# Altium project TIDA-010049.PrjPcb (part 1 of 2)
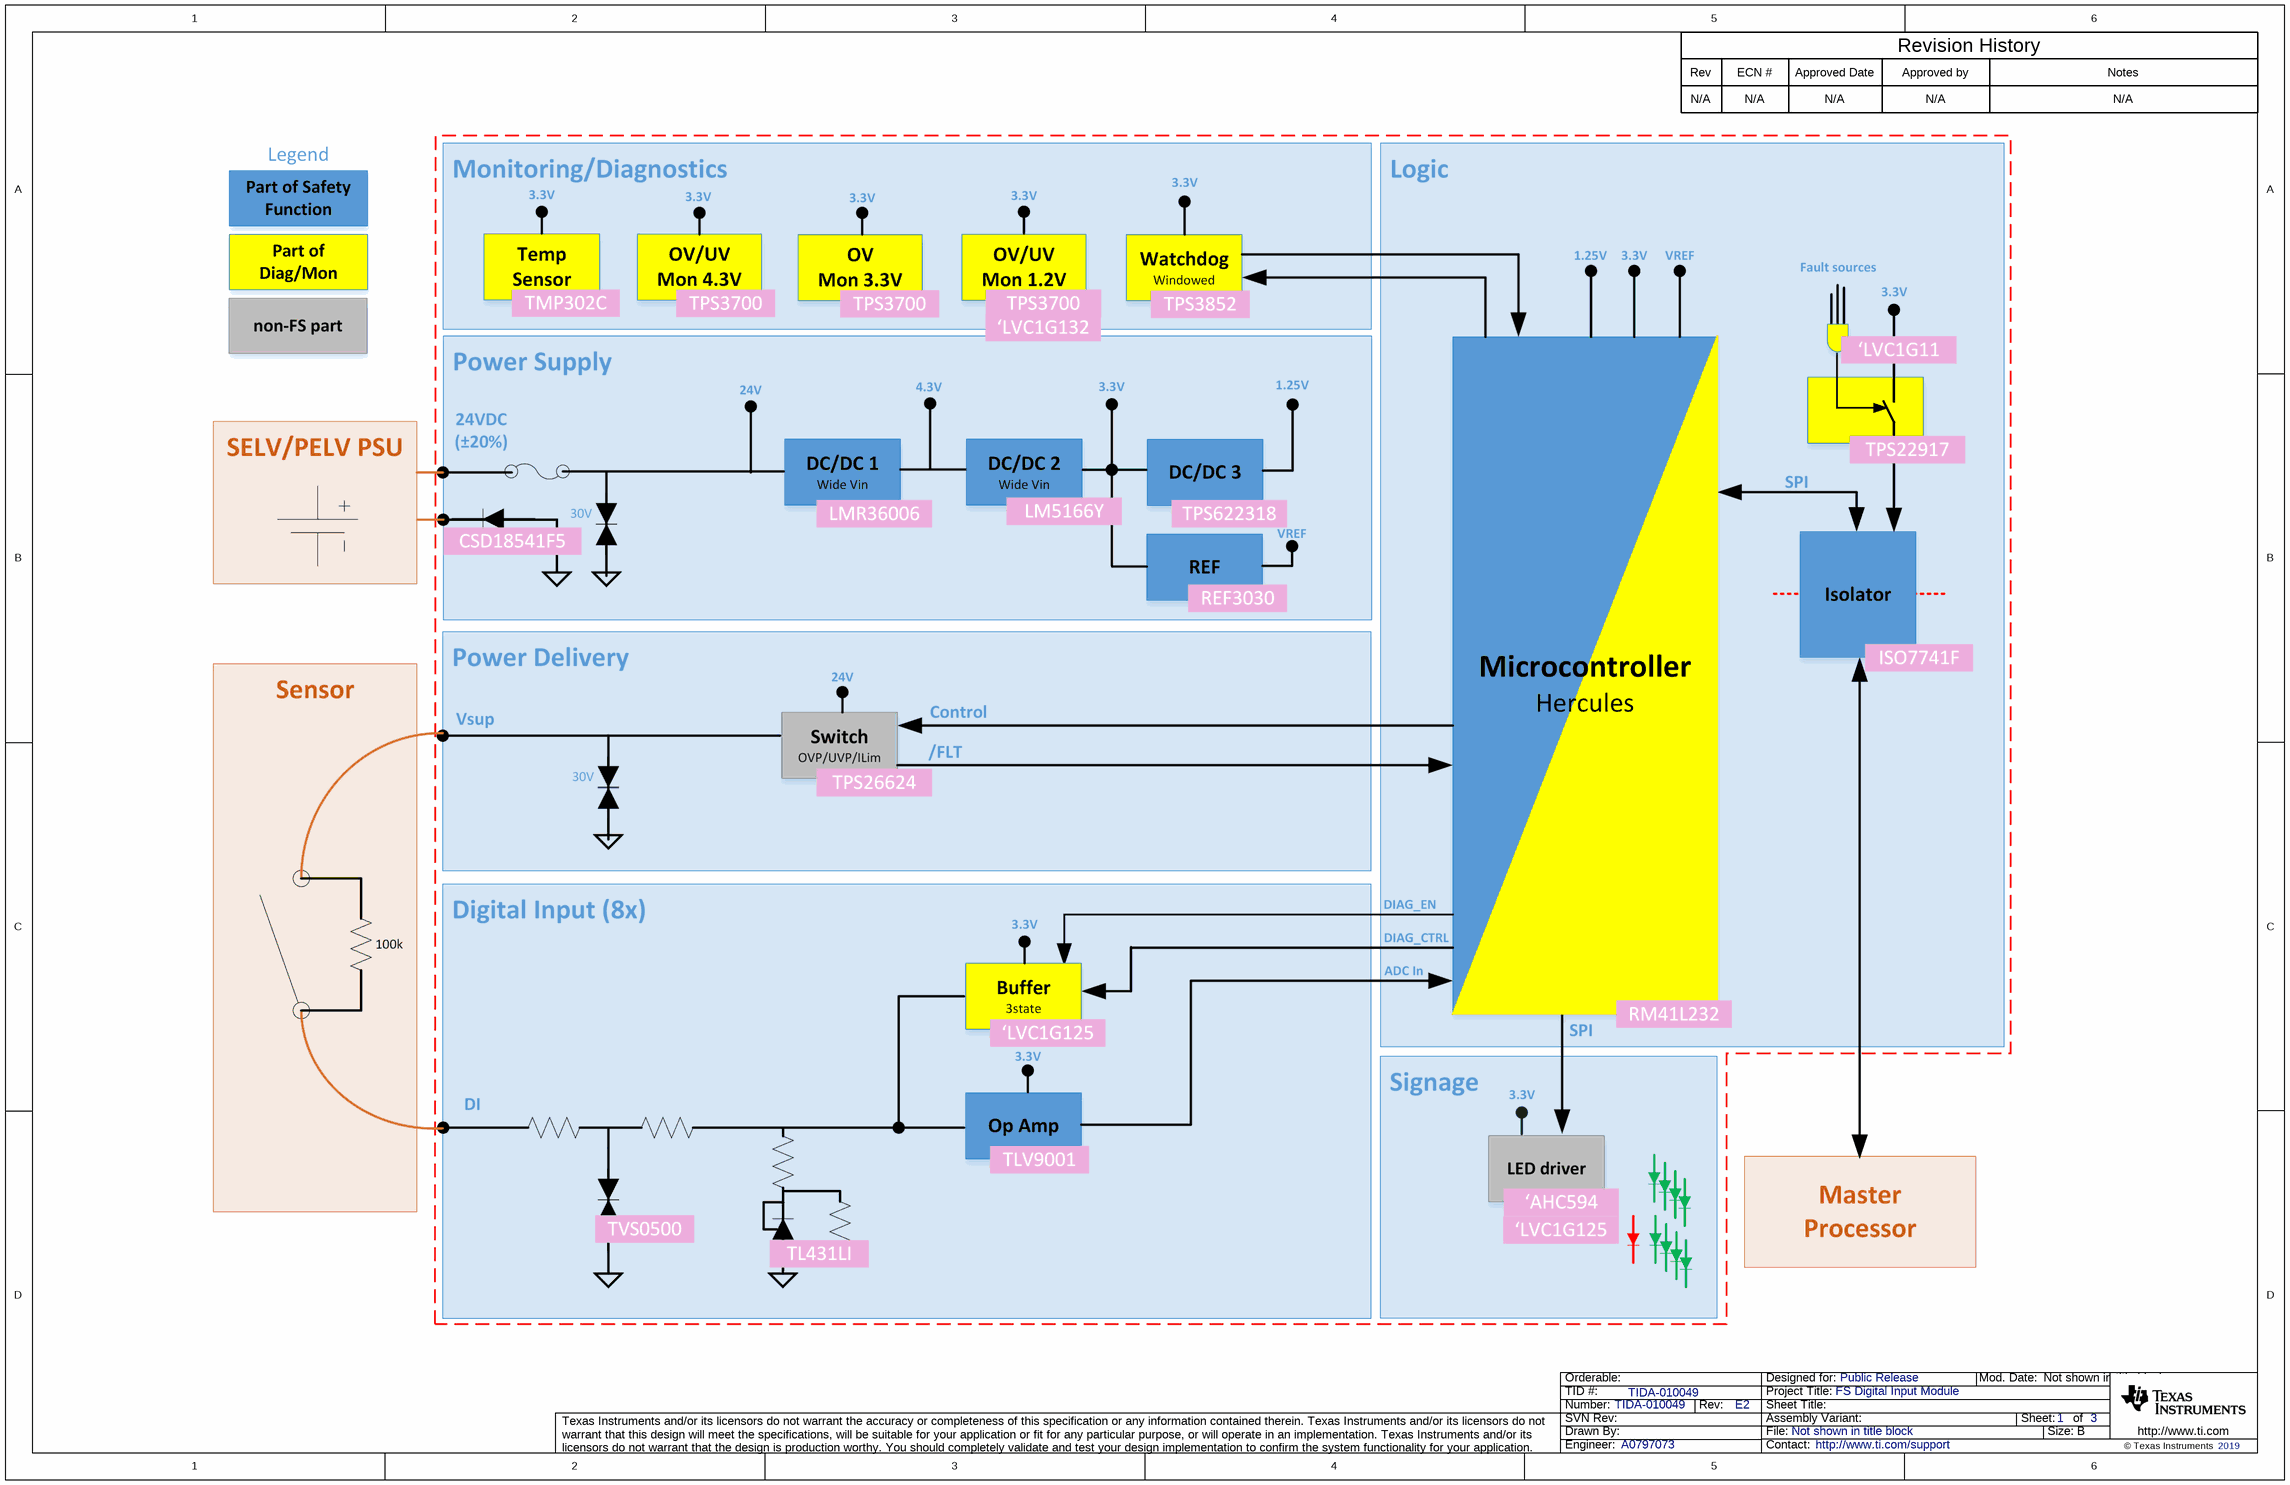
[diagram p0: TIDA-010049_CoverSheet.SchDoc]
CopyrightYear: 2019; PCB_Layout: A0797073; PCB_Rev: E2; PRJ_Customer: Public Release; PRJ_Engineer: A0797073; PRJ_Number: TIDA-010049; PRJ_Title: FS Digital Input Module; SCH_Rev: E2; TechSupport: http://www.ti.com/support; TID: TIDA-010049
7 sheets, 310 parts. Net scope: hierarchical (ports join the sheet entries above them; power ports are global).
Board file: TIDA-010049.PcbDoc
Sheets:
  TIDA-010049_CoverSheet.SchDoc
  TIDA-010049_Top.SchDoc
    U_TIDACBL-0053_Hercules = TIDA-010049_Hercules.SchDoc
    U_TIDACBL-0053_Power = TIDA-010049_Power.SchDoc
    DI1 = TIDA-010049_DigitalInputChan.SchDoc
    DI2 = TIDA-010049_DigitalInputChan.SchDoc
    DI3 = TIDA-010049_DigitalInputChan.SchDoc
    DI4 = TIDA-010049_DigitalInputChan.SchDoc
    DI5 = TIDA-010049_DigitalInputChan.SchDoc
    DI6 = TIDA-010049_DigitalInputChan.SchDoc
    DI7 = TIDA-010049_DigitalInputChan.SchDoc
    DI8 = TIDA-010049_DigitalInputChan.SchDoc
    U_TIDACBL-0053_LED = TIDA-010049_LED.SchDoc
    U_TIDA-010049_Hardware = TIDA-010049_Hardware.SchDoc

## Sheet TIDA-010049_CoverSheet.SchDoc
size 431 x 279 mm; Date: Not shown in title block; ApprovedBy: Not shown in title block; CheckedBy: Not shown in title block; Author: Not shown in title block; CompanyName: Not shown in title block; Engineer: Not shown in title block; Organization: Not shown in title block; Address1: Not shown in title block; Address2: Not shown in title block; Address3: Not shown in title block; Address4: Not shown in title block; DocumentNumber: 1; Revision: Use project parameter SCH_Rev; SheetNumber: 1; SheetTotal: 3; PageSetup: Record=PageOptions¦CenterHorizontal=True¦CenterVertical=True¦PrintScale=1.00¦XCorrection=1.00¦YCorrection=1.00¦PrintKind=0¦BorderSize=5000000¦LeftOffset=0¦BottomOffset=0¦Orientation=2¦PaperLength=1000¦PaperWidth=1000¦Scale=100¦PaperSource=15¦PrintQuality=600¦MediaType=1¦DitherType=10¦PaperKind=Letter¦PrintScaleMode=1

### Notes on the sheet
- Rev
- N/A
- ECN #
- Approved Date
- Approved by
- Revision History
- Notes

## Sheet TIDA-010049_Top.SchDoc
size 431 x 279 mm; Date: Not shown in title block; ApprovedBy: Not shown in title block; CheckedBy: Not shown in title block; Author: Not shown in title block; CompanyName: Not shown in title block; Engineer: Not shown in title block; Organization: Not shown in title block; Address1: Not shown in title block; Address2: Not shown in title block; Address3: Not shown in title block; Address4: Not shown in title block; DocumentNumber: 2; Revision: Use project parameter SCH_Rev; SheetNumber: 2; SheetTotal: 3; PageSetup: Record=PageOptions¦CenterHorizontal=True¦CenterVertical=True¦PrintScale=1.00¦XCorrection=1.00¦YCorrection=1.00¦PrintKind=0¦BorderSize=5000000¦LeftOffset=0¦BottomOffset=0¦Orientation=2¦PaperLength=1000¦PaperWidth=1000¦Scale=100¦PaperSource=15¦PrintQuality=600¦MediaType=1¦DitherType=10¦PaperKind=Letter¦PrintScaleMode=1
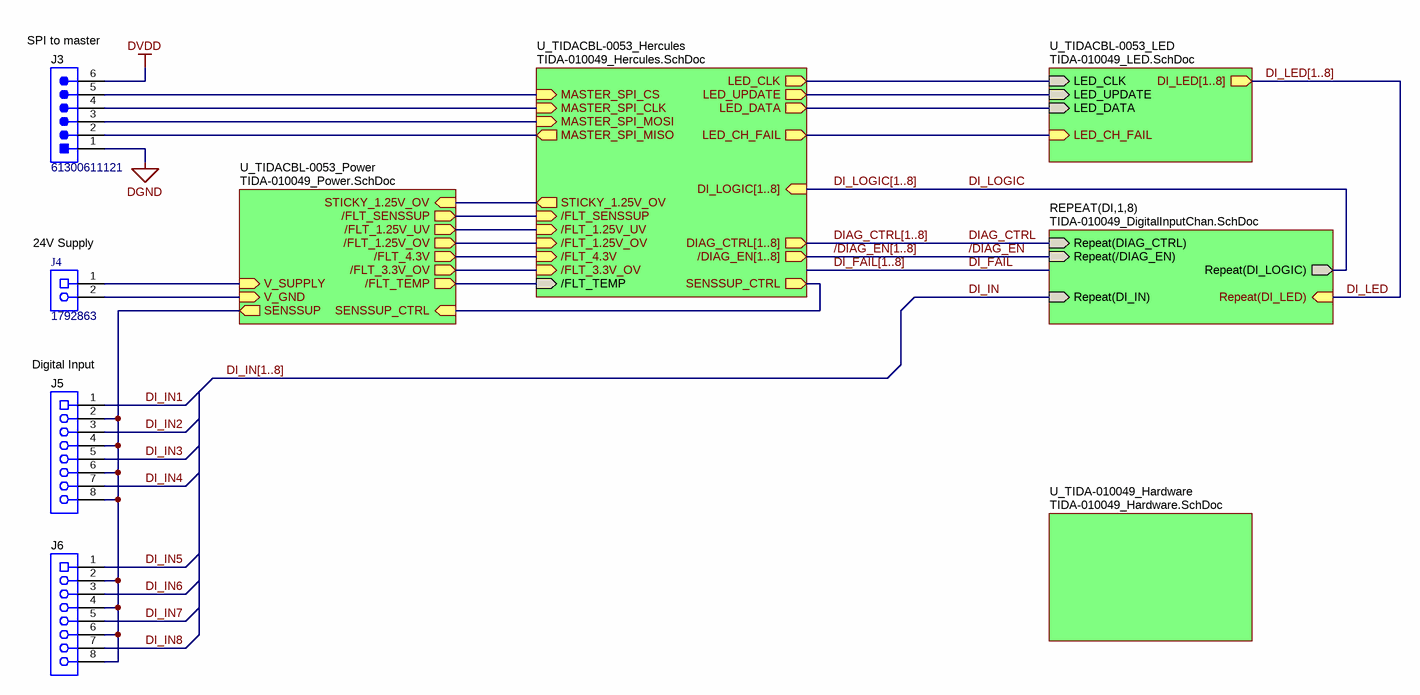
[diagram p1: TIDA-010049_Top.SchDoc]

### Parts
J3  61300611121  [WURTH_61300611121]
J4  1792863  [Phoenix_1792863]
J5  1990067  [Phoenix_1990067]  (value not drawn)
J6  1990067  [Phoenix_1990067]  (value not drawn)

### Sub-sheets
REPEAT(DI,1,8) = TIDA-010049_DigitalInputChan.SchDoc: Repeat(DI_IN) (in), Repeat(/DIAG_EN) (in), Repeat(DIAG_CTRL) (in), Repeat(DI_LOGIC) (out), Repeat(DI_LED) (in)
U_TIDA-010049_Hardware = TIDA-010049_Hardware.SchDoc: no entries
U_TIDACBL-0053_Hercules = TIDA-010049_Hercules.SchDoc: /FLT_TEMP (in), DIAG_CTRL[1..8] (out), /DIAG_EN[1..8] (out), MASTER_SPI_CLK (in), MASTER_SPI_MISO (out), MASTER_SPI_CS (in), MASTER_SPI_MOSI (in), /FLT_3.3V_OV (in), DI_LOGIC[1..8] (in), LED_CH_FAIL (out), LED_CLK (out), LED_DATA (out), LED_UPDATE (out), /FLT_4.3V (in), /FLT_SENSSUP (in), /FLT_1.25V_OV (in), SENSSUP_CTRL (out), STICKY_1.25V_OV (out), /FLT_1.25V_UV (in)
U_TIDACBL-0053_LED = TIDA-010049_LED.SchDoc: LED_UPDATE (in), LED_CLK (in), LED_DATA (in), LED_CH_FAIL (in), DI_LED[1..8] (out)
U_TIDACBL-0053_Power = TIDA-010049_Power.SchDoc: /FLT_TEMP (out), V_SUPPLY (in), /FLT_3.3V_OV (out), V_GND (in), /FLT_4.3V (out), SENSSUP (out), /FLT_SENSSUP (out), SENSSUP_CTRL (in), /FLT_1.25V_OV (out), /FLT_1.25V_UV (out), STICKY_1.25V_OV (in)

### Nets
DGND: J3.1
DVDD: J3.6
/FLT_1.25V_OV: sheet U_TIDACBL-0053_Hercules//FLT_1.25V_OV, sheet U_TIDACBL-0053_Power//FLT_1.25V_OV
/FLT_1.25V_UV: sheet U_TIDACBL-0053_Hercules//FLT_1.25V_UV, sheet U_TIDACBL-0053_Power//FLT_1.25V_UV
/FLT_3.3V_OV: sheet U_TIDACBL-0053_Hercules//FLT_3.3V_OV, sheet U_TIDACBL-0053_Power//FLT_3.3V_OV
/FLT_4.3V: sheet U_TIDACBL-0053_Hercules//FLT_4.3V, sheet U_TIDACBL-0053_Power//FLT_4.3V
/FLT_SENSSUP: sheet U_TIDACBL-0053_Hercules//FLT_SENSSUP, sheet U_TIDACBL-0053_Power//FLT_SENSSUP
/FLT_TEMP: sheet U_TIDACBL-0053_Hercules//FLT_TEMP, sheet U_TIDACBL-0053_Power//FLT_TEMP
DI_IN1: J5.1
DI_IN2: J5.3
DI_IN3: J5.5
DI_IN4: J5.7
DI_IN5: J6.1
DI_IN6: J6.3
DI_IN7: J6.5
DI_IN8: J6.7
LED_CH_FAIL: sheet U_TIDACBL-0053_Hercules/LED_CH_FAIL, sheet U_TIDACBL-0053_LED/LED_CH_FAIL
LED_CLK: sheet U_TIDACBL-0053_Hercules/LED_CLK, sheet U_TIDACBL-0053_LED/LED_CLK
LED_DATA: sheet U_TIDACBL-0053_Hercules/LED_DATA, sheet U_TIDACBL-0053_LED/LED_DATA
LED_UPDATE: sheet U_TIDACBL-0053_Hercules/LED_UPDATE, sheet U_TIDACBL-0053_LED/LED_UPDATE
MASTER_SPI_CLK: J3.4 ; sheet U_TIDACBL-0053_Hercules/MASTER_SPI_CLK
MASTER_SPI_CS: J3.5 ; sheet U_TIDACBL-0053_Hercules/MASTER_SPI_CS
MASTER_SPI_MISO: J3.2 ; sheet U_TIDACBL-0053_Hercules/MASTER_SPI_MISO
MASTER_SPI_MOSI: J3.3 ; sheet U_TIDACBL-0053_Hercules/MASTER_SPI_MOSI
SENSSUP: J5.2 J5.4 J5.6 J5.8 J6.2 J6.4 J6.6 J6.8 ; sheet U_TIDACBL-0053_Power/SENSSUP
SENSSUP_CTRL: sheet U_TIDACBL-0053_Hercules/SENSSUP_CTRL, sheet U_TIDACBL-0053_Power/SENSSUP_CTRL
STICKY_1.25V_OV: sheet U_TIDACBL-0053_Hercules/STICKY_1.25V_OV, sheet U_TIDACBL-0053_Power/STICKY_1.25V_OV
V_GND: J4.2 ; sheet U_TIDACBL-0053_Power/V_GND
V_SUPPLY: J4.1 ; sheet U_TIDACBL-0053_Power/V_SUPPLY

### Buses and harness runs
bus /DIAG_EN[1..8] = sheet U_TIDACBL-0053_Hercules//DIAG_EN[1..8]
bus DI_FAIL[1..8]
bus DI_IN[1..8]
bus DI_LED[1..8] = sheet U_TIDACBL-0053_LED/DI_LED[1..8]
bus DI_LOGIC[1..8] = sheet U_TIDACBL-0053_Hercules/DI_LOGIC[1..8]
bus DIAG_CTRL[1..8] = sheet U_TIDACBL-0053_Hercules/DIAG_CTRL[1..8]

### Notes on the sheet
- (near J3) SPI to master
- (near J4) 24V Supply
- (near J5) Digital Input

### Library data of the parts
J3 = CMP-0054801-2: Header, 2.54 mm, 6x1, Gold, TH; Manufacturer: Wurth Elektronik; Cert_UL: Y; Gender: Male; Row_Count: 1; Shrouded: N; Pitch_mm: 2.54
J4 = CMP-0055529-1: Terminal Block, 5mm, 2x1, R/A, TH; Manufacturer: Phoenix Contact; Cert_VDE: Y; CNHeader: FALSE; Current_A: 16A; Gender: Female; Voltage_V: 400V; Row_Count: 1; Pitch_mm: 5; CT: TRUE
J5 J6 = CMP-0055509-1: Terminal Block, 8x1, 2.5mm, Green, TH; Manufacturer: Phoenix Contact; CNHeader: FALSE; Current_A: 2A; Gender: Female; Cert_CSA: Y; Voltage_V: 300V; Row_Count: 1; Pitch_mm: 2.5; CT: TRUE

## Sheet TIDA-010049_Hercules.SchDoc
size 431 x 279 mm; Date: Not shown in title block; ApprovedBy: Not shown in title block; CheckedBy: Not shown in title block; Author: Not shown in title block; CompanyName: Not shown in title block; Engineer: Not shown in title block; Organization: Not shown in title block; Address1: Not shown in title block; Address2: Not shown in title block; Address3: Not shown in title block; Address4: Not shown in title block; DocumentNumber: 2; Revision: Use project parameter SCH_Rev; SheetNumber: 2; SheetTotal: 3; PageSetup: Record=PageOptions¦CenterHorizontal=True¦CenterVertical=True¦PrintScale=1.00¦XCorrection=1.00¦YCorrection=1.00¦PrintKind=0¦BorderSize=5000000¦LeftOffset=0¦BottomOffset=0¦Orientation=2¦PaperLength=1000¦PaperWidth=1000¦Scale=100¦PaperSource=15¦PrintQuality=600¦MediaType=1¦DitherType=10¦PaperKind=Letter¦PrintScaleMode=1
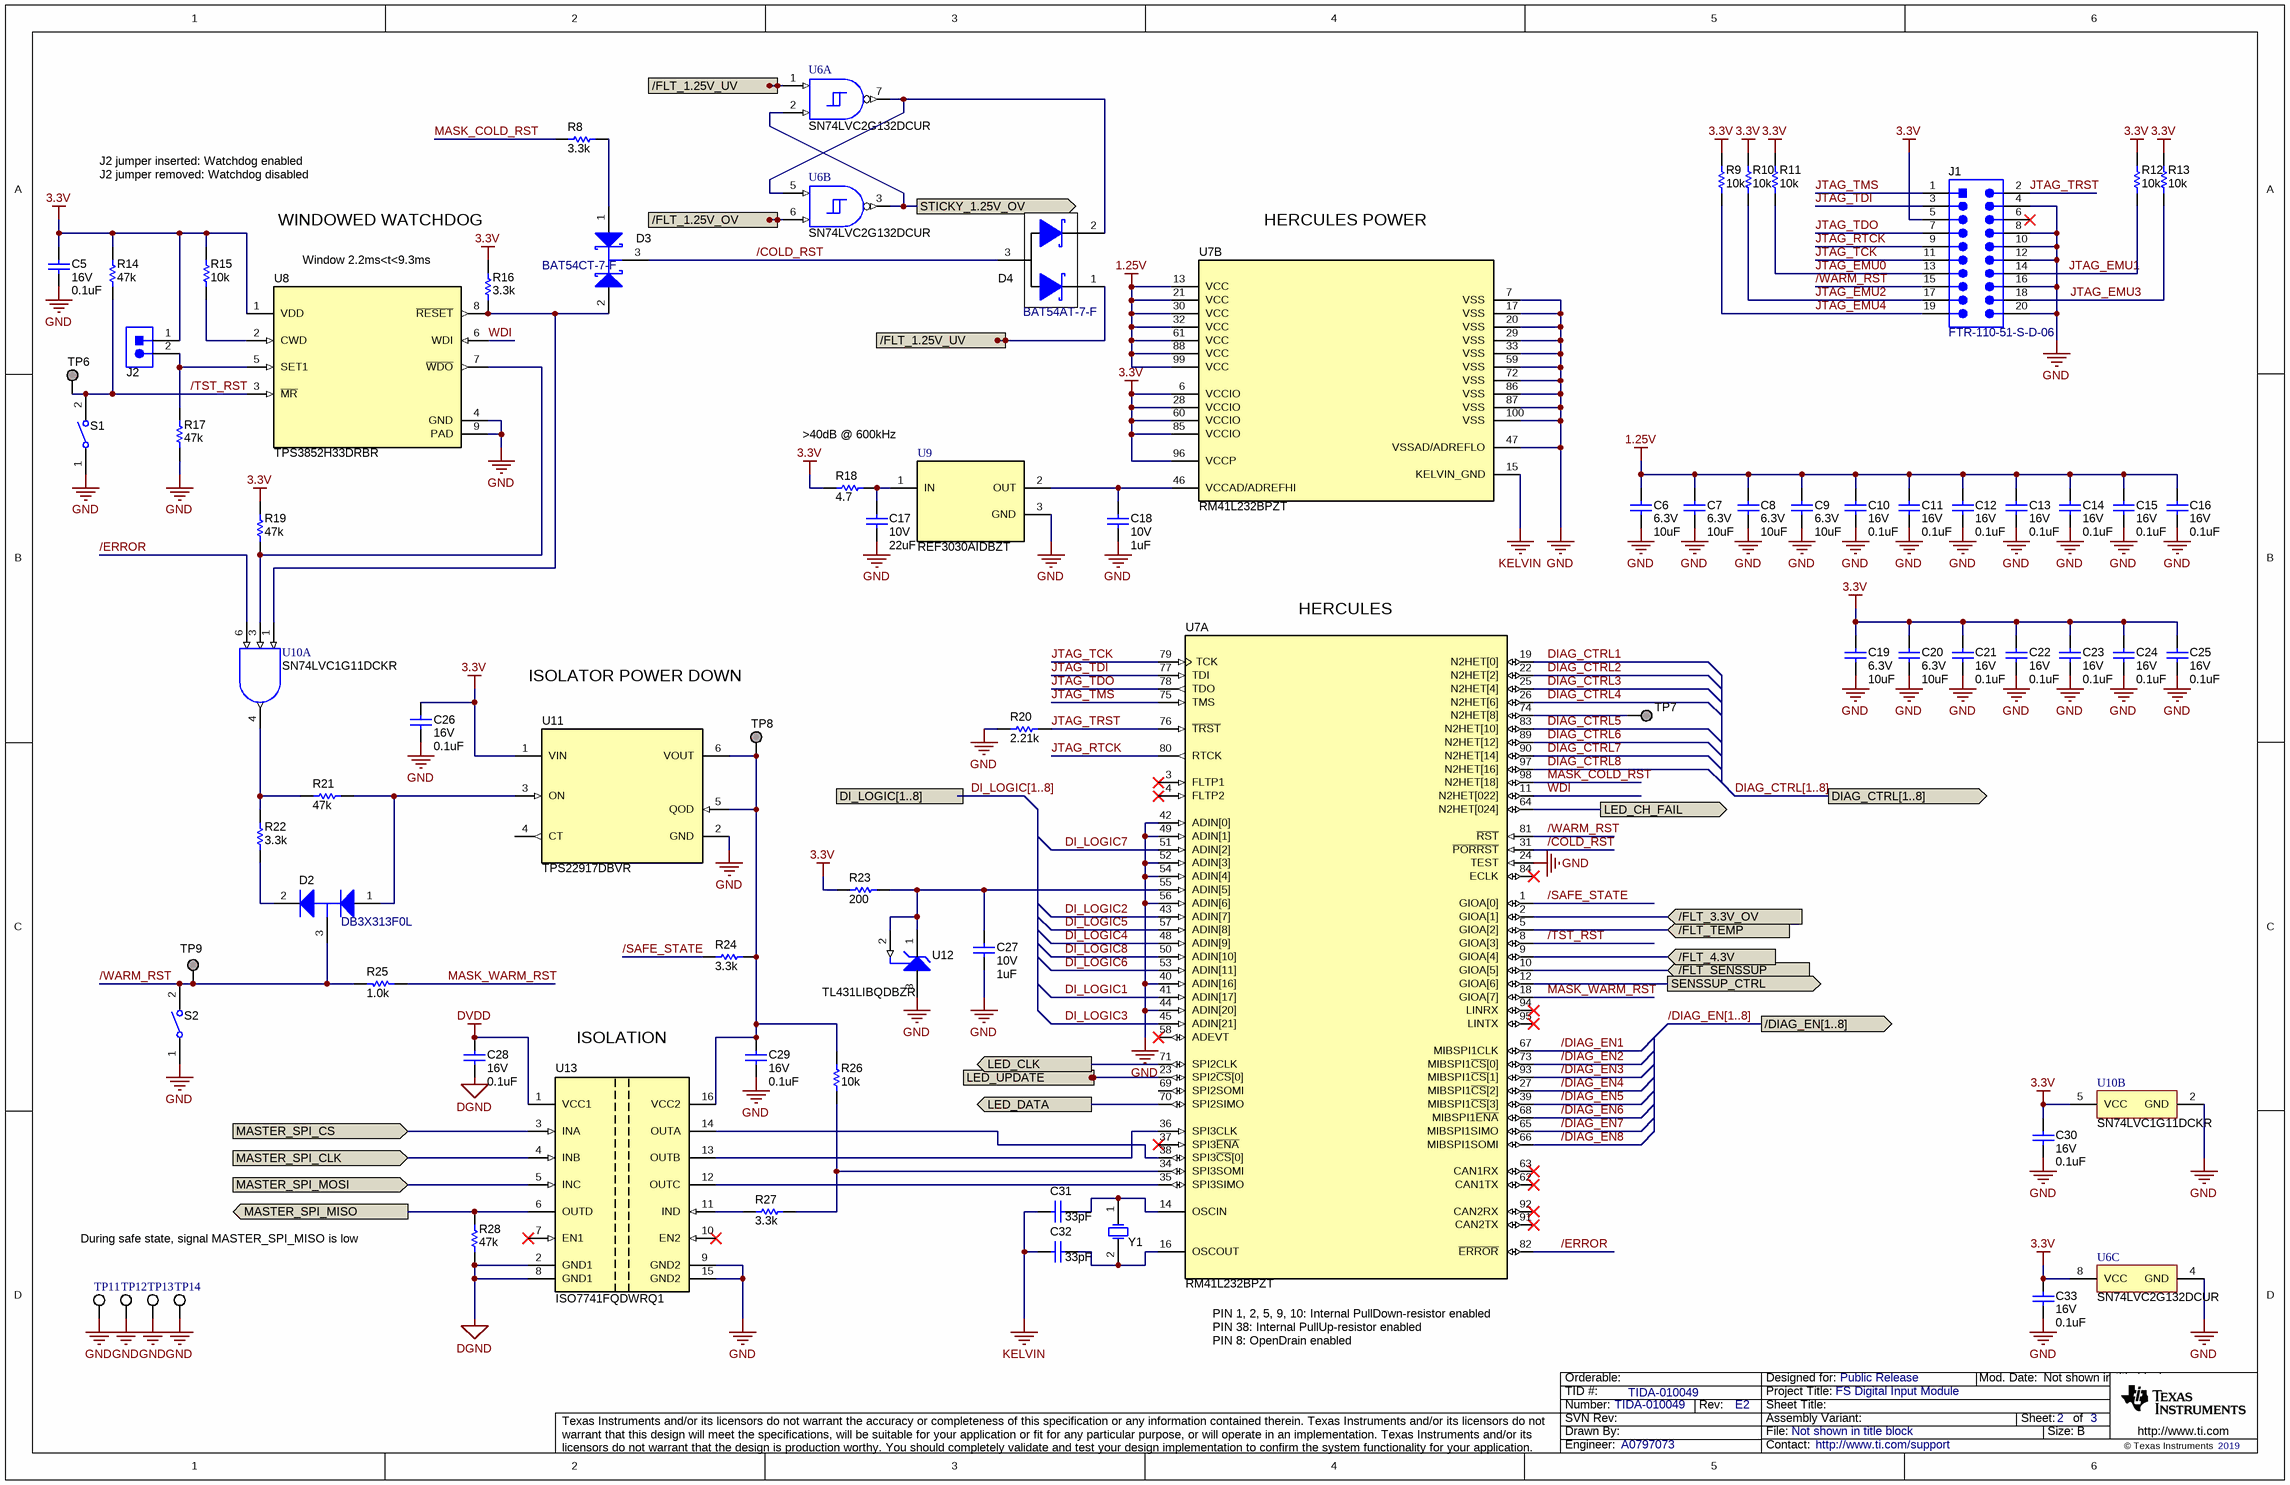
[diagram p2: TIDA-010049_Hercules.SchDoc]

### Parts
C5  VDC_V: 16V  ValueDisplayed: 0.1uF  [0603]  (hidden comment: GRM188R71C104KA01D)
C6  VDC_V: 6.3V  ValueDisplayed: 10uF  [0805_HV]  (hidden comment: JMK212B7106KG-T)
C7  VDC_V: 6.3V  ValueDisplayed: 10uF  [0805_HV]  (hidden comment: JMK212B7106KG-T)
C8  VDC_V: 6.3V  ValueDisplayed: 10uF  [0805_HV]  (hidden comment: JMK212B7106KG-T)
C9  VDC_V: 6.3V  ValueDisplayed: 10uF  [0805_HV]  (hidden comment: JMK212B7106KG-T)
C10  VDC_V: 16V  ValueDisplayed: 0.1uF  [0603]  (hidden comment: GRM188R71C104KA01D)
C11  VDC_V: 16V  ValueDisplayed: 0.1uF  [0603]  (hidden comment: GRM188R71C104KA01D)
C12  VDC_V: 16V  ValueDisplayed: 0.1uF  [0603]  (hidden comment: GRM188R71C104KA01D)
C13  VDC_V: 16V  ValueDisplayed: 0.1uF  [0603]  (hidden comment: GRM188R71C104KA01D)
C14  VDC_V: 16V  ValueDisplayed: 0.1uF  [0603]  (hidden comment: GRM188R71C104KA01D)
C15  VDC_V: 16V  ValueDisplayed: 0.1uF  [0603]  (hidden comment: GRM188R71C104KA01D)
C16  VDC_V: 16V  ValueDisplayed: 0.1uF  [0603]  (hidden comment: GRM188R71C104KA01D)
C17  VDC_V: 10V  ValueDisplayed: 22uF  [0805_HV]  (hidden comment: GRM21BZ71A226ME15L)
C18  VDC_V: 10V  ValueDisplayed: 1uF  [0603]  (hidden comment: GRM188R71A105KA61D)
C19  VDC_V: 6.3V  ValueDisplayed: 10uF  [0805_HV]  (hidden comment: JMK212B7106KG-T)
C20  VDC_V: 6.3V  ValueDisplayed: 10uF  [0805_HV]  (hidden comment: JMK212B7106KG-T)
C21  VDC_V: 16V  ValueDisplayed: 0.1uF  [0603]  (hidden comment: GRM188R71C104KA01D)
C22  VDC_V: 16V  ValueDisplayed: 0.1uF  [0603]  (hidden comment: GRM188R71C104KA01D)
C23  VDC_V: 16V  ValueDisplayed: 0.1uF  [0603]  (hidden comment: GRM188R71C104KA01D)
C24  VDC_V: 16V  ValueDisplayed: 0.1uF  [0603]  (hidden comment: GRM188R71C104KA01D)
C25  VDC_V: 16V  ValueDisplayed: 0.1uF  [0603]  (hidden comment: GRM188R71C104KA01D)
C26  VDC_V: 16V  ValueDisplayed: 0.1uF  [0603]  (hidden comment: GRM188R71C104KA01D)
C27  VDC_V: 10V  ValueDisplayed: 1uF  [0603]  (hidden comment: GRM188R71A105KA61D)
C28  VDC_V: 16V  ValueDisplayed: 0.1uF  [0603]  (hidden comment: GRM188R71C104KA01D)
C29  VDC_V: 16V  ValueDisplayed: 0.1uF  [0603]  (hidden comment: GRM188R71C104KA01D)
C30  VDC_V: 16V  ValueDisplayed: 0.1uF  [0603]  (hidden comment: GRM188R71C104KA01D)
C31  ValueDisplayed: 33pF  [0603]  (hidden comment: GRM1885C1H330JA01D)
C32  ValueDisplayed: 33pF  [0603]  (hidden comment: GRM1885C1H330JA01D)
C33  VDC_V: 16V  ValueDisplayed: 0.1uF  [0603]  (hidden comment: GRM188R71C104KA01D)
D2  DB3X313F0L  [Mini3-G3-B]
D3  BAT54CT-7-F  [SOT-523]
D4  BAT54AT-7-F  [SOT-523]
J1  FTR-110-51-S-D-06  [Samtec_FTR-110-51-x-D-06]
J2  HTSW-102-07-G-S  [Samtec_HTSW-102-07-G-S]  (value not drawn)
R8  ValueDisplayed: 3.3k  [0603]  (hidden comment: RC0603JR-073K3L)
R9  ValueDisplayed: 10k  [0603]  (hidden comment: RC0603JR-0710KL)
R10  ValueDisplayed: 10k  [0603]  (hidden comment: RC0603JR-0710KL)
R11  ValueDisplayed: 10k  [0603]  (hidden comment: RC0603JR-0710KL)
R12  ValueDisplayed: 10k  [0603]  (hidden comment: RC0603JR-0710KL)
R13  ValueDisplayed: 10k  [0603]  (hidden comment: RC0603JR-0710KL)
R14  ValueDisplayed: 47k  [0603]  (hidden comment: RC0603JR-0747KL)
R15  ValueDisplayed: 10k  [0603]  (hidden comment: RC0603JR-0710KL)
R16  ValueDisplayed: 3.3k  [0603]  (hidden comment: RC0603JR-073K3L)
R17  ValueDisplayed: 47k  [0603]  (hidden comment: RC0603JR-0747KL)
R18  ValueDisplayed: 4.7  [0603]  (hidden comment: CRCW06034R70JNEA)
R19  ValueDisplayed: 47k  [0603]  (hidden comment: RC0603JR-0747KL)
R20  ValueDisplayed: 2.21k  [0603]  (hidden comment: RC0603FR-072K21L)
R21  ValueDisplayed: 47k  [0603]  (hidden comment: RC0603JR-0747KL)
R22  ValueDisplayed: 3.3k  [0603]  (hidden comment: RC0603JR-073K3L)
R23  ValueDisplayed: 200  [0603]  (hidden comment: CRCW0603200RJNEA)
R24  ValueDisplayed: 3.3k  [0603]  (hidden comment: RC0603JR-073K3L)
R25  ValueDisplayed: 1.0k  [0603]  (hidden comment: RC0603JR-071KL)
R26  ValueDisplayed: 10k  [0603]  (hidden comment: RC0603JR-0710KL)
R27  ValueDisplayed: 3.3k  [0603]  (hidden comment: RC0603JR-073K3L)
R28  ValueDisplayed: 47k  [0603]  (hidden comment: RC0603JR-0747KL)
S1  RS-032G05A3-SM RT  [SW_RS-032G05A3-SM]  (value not drawn)
S2  RS-032G05A3-SM RT  [SW_RS-032G05A3-SM]  (value not drawn)
TP6  TP_SM_1MM  [TP_SM_1MM]  (value not drawn)  (no BOM)
TP7  TP_SM_1MM  [TP_SM_1MM]  (value not drawn)  (no BOM)
TP8  TP_SM_1MM  [TP_SM_1MM]  (value not drawn)  (no BOM)
TP9  TP_SM_1MM  [TP_SM_1MM]  (value not drawn)  (no BOM)
TP11  5015  [Testpoint_Keystone_Miniature]  (value not drawn)
TP12  5015  [Testpoint_Keystone_Miniature]  (value not drawn)
TP13  5015  [Testpoint_Keystone_Miniature]  (value not drawn)
TP14  5015  [Testpoint_Keystone_Miniature]  (value not drawn)
U6  SN74LVC2G132DCUR  [DCU0008A_N]  (parts A,B,C of 3)
U7  RM41L232BPZT  [PZ0100A_M]  (parts A,B of 2)
U8  TPS3852H33DRBR  [DRB0008A]
U9  REF3030AIDBZT  [DBZ0003A_N]
U10  SN74LVC1G11DCKR  [DCK0006A_N]  (parts A,B of 2)
U11  TPS22917DBVR  [DBV0006A_N]
U12  TL431LIBQDBZR  [DBZ0003A_N]
U13  ISO7741FQDWRQ1  [DW0016B_HV]
Y1  ABM3-16.000MHZ-D2Y-T  [XTAL_ABM3]  (value not drawn)

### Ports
/DIAG_EN[1..8] (out), /FLT_1.25V_OV (in), /FLT_1.25V_UV (in), /FLT_3.3V_OV (in), /FLT_4.3V (in), /FLT_SENSSUP (in), /FLT_TEMP (in), DI_LOGIC[1..8] (in), DIAG_CTRL[1..8] (out), LED_CH_FAIL (out), LED_CLK (out), LED_DATA (out), LED_UPDATE (out), MASTER_SPI_CLK (in), MASTER_SPI_CS (in), MASTER_SPI_MISO (out), MASTER_SPI_MOSI (in), SENSSUP_CTRL (out), STICKY_1.25V_OV (out)

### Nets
1.25V: C6.1 C7.1 C8.1 C9.1 C10.1 C11.1 C12.1 C13.1 C14.1 C15.1 C16.1 U7.13(VCC) U7.21(VCC) U7.30(VCC) U7.32(VCC) U7.61(VCC) U7.88(VCC) U7.99(VCC)
3.3V: C5.1 C19.1 C20.1 C21.1 C22.1 C23.1 C24.1 C25.1 C26.1 C30.1 C33.1 J1.5 J2.1 R9.2 R10.2 R11.2 R12.2 R13.2 R14.2 R15.2 R16.1 R18.1 R19.2 R23.2 U6.8(VCC) U7.6(VCCIO) U7.28(VCCIO) U7.60(VCCIO) U7.85(VCCIO) U7.96(VCCP) U8.1(VDD) U10.5(VCC) U11.1(VIN)
DGND: C28.2 R28.2 U13.2(GND1) U13.8(GND1)
DVDD: C28.1 U13.1(VCC1)
GND: C5.2 C6.2 C7.2 C8.2 C9.2 C10.2 C11.2 C12.2 C13.2 C14.2 C15.2 C16.2 C17.2 C18.2 C19.2 C20.2 C21.2 C22.2 C23.2 C24.2 C25.2 C26.2 C27.2 C29.2 C30.2 C33.2 J1.4 J1.8 J1.10 J1.12 J1.16 J1.20 R17.1 R20.1 S1.1 S2.1 TP11.1 TP12.1 TP13.1 TP14.1 U6.4(GND) U7.7(VSS) U7.17(VSS) U7.20(VSS) U7.24(TEST) U7.29(VSS) U7.33(VSS) U7.40(ADIN[16]) U7.42(ADIN[0]) U7.44(ADIN[20]) U7.47(VSSAD/ADREFLO) U7.49(ADIN[1]) U7.52(ADIN[3]) U7.54(ADIN[4]) U7.56(ADIN[6]) U7.59(VSS) U7.72(VSS) U7.86(VSS) U7.87(VSS) U7.100(VSS) U8.4(GND) U8.9(PAD) U9.3(GND) U10.2(GND) U11.2(GND) U12.3(ANODE) U13.9(GND2) U13.15(GND2)
KELVIN: C31.2 C32.2 U7.15(KELVIN_GND)
/COLD_RST: D3.3(K) D4.3(A) U7.31(~{PORRST})
/DIAG_EN1: U7.67(MIBSPI1CLK)
/DIAG_EN2: U7.73(MIBSPI1~{CS}[0])
/DIAG_EN3: U7.93(MIBSPI1~{CS}[1])
/DIAG_EN4: U7.27(MIBSPI1~{CS}[2])
/DIAG_EN5: U7.39(MIBSPI1~{CS}[3])
/DIAG_EN6: U7.68(MIBSPI1~{ENA})
/DIAG_EN7: U7.65(MIBSPI1SIMO)
/DIAG_EN8: U7.66(MIBSPI1SOMI)
/ERROR: U7.82(~{ERROR}) U10.6(C)
/FLT_1.25V_OV: U6.6(2B) ; port /FLT_1.25V_OV
/FLT_1.25V_UV: D4.1(A) U6.1(1A) ; port /FLT_1.25V_UV
/FLT_3.3V_OV: U7.2(GIOA[1]) ; port /FLT_3.3V_OV
/FLT_4.3V: U7.9(GIOA[4]) ; port /FLT_4.3V
/FLT_SENSSUP: U7.10(GIOA[5]) ; port /FLT_SENSSUP
/FLT_TEMP: U7.5(GIOA[2]) ; port /FLT_TEMP
/SAFE_STATE: R24.2 U7.1(GIOA[0])
/TST_RST: R14.1 S1.2 TP6.1 U7.8(GIOA[3]) U8.3(~{MR})
/WARM_RST: D2.3(C) J1.15 R25.2 S2.2 TP9.1 U7.81(~{RST})
DI_LOGIC1: U7.41(ADIN[17])
DI_LOGIC2: U7.43(ADIN[7])
DI_LOGIC3: U7.45(ADIN[21])
DI_LOGIC4: U7.48(ADIN[9])
DI_LOGIC5: U7.57(ADIN[8])
DI_LOGIC6: U7.53(ADIN[11])
DI_LOGIC7: U7.51(ADIN[2])
DI_LOGIC8: U7.50(ADIN[10])
DIAG_CTRL1: U7.19(N2HET[0])
DIAG_CTRL2: U7.22(N2HET[2])
DIAG_CTRL3: U7.25(N2HET[4])
DIAG_CTRL4: U7.26(N2HET[6])
DIAG_CTRL5: U7.83(N2HET[10])
DIAG_CTRL6: U7.89(N2HET[12])
DIAG_CTRL7: U7.90(N2HET[14])
DIAG_CTRL8: U7.97(N2HET[16])
JTAG_EMU0: J1.13 R11.1
JTAG_EMU1: J1.14 R12.1
JTAG_EMU2: J1.17 R10.1
JTAG_EMU3: J1.18 R13.1
JTAG_EMU4: J1.19 R9.1
JTAG_RTCK: J1.9 U7.80(RTCK)
JTAG_TCK: J1.11 U7.79(TCK)
JTAG_TDI: J1.3 U7.77(TDI)
JTAG_TDO: J1.7 U7.78(TDO)
JTAG_TMS: J1.1 U7.75(TMS)
JTAG_TRST: J1.2 R20.2 U7.76(~{TRST})
LED_CH_FAIL: U7.64(N2HET[024]) ; port LED_CH_FAIL
LED_CLK: U7.71(SPI2CLK) ; port LED_CLK
LED_DATA: U7.70(SPI2SIMO) ; port LED_DATA
LED_UPDATE: U7.23(SPI2~{CS}[0]) ; port LED_UPDATE
MASK_COLD_RST: R8.1 U7.98(N2HET[18])
MASK_WARM_RST: R25.1 U7.18(GIOA[7])
MASTER_SPI_CLK: U13.4(INB) ; port MASTER_SPI_CLK
MASTER_SPI_CS: U13.3(INA) ; port MASTER_SPI_CS
MASTER_SPI_MISO: R28.1 U13.6(OUTD) ; port MASTER_SPI_MISO
MASTER_SPI_MOSI: U13.5(INC) ; port MASTER_SPI_MOSI
SENSSUP_CTRL: U7.12(GIOA[6]) ; port SENSSUP_CTRL
STICKY_1.25V_OV: U6.2(1B) U6.3(2Y) ; port STICKY_1.25V_OV
WDI: U7.11(N2HET[022]) U8.6(WDI)
NetC17_1: C17.1 R18.2 U9.1(IN)
NetC18_1: C18.1 U7.46(VCCAD/ADREFHI) U9.2(OUT)
NetC27_1: C27.1 R23.1 U7.55(ADIN[5]) U12.1(CATHODE) U12.2(REF)
NetC29_1: C29.1 R24.1 R26.2 TP8.1 U11.5(QOD) U11.6(VOUT) U13.16(VCC2)
NetC31_1: C31.1 U7.14(OSCIN) Y1.1(OSC1)
NetC32_1: C32.1 U7.16(OSCOUT) Y1.2(OSC2)
NetD2_1: D2.1(A) R21.1 U11.3(ON)
NetD2_2: D2.2(K) R22.2
NetD3_1: D3.1(A1) R8.2
NetD3_2: D3.2(A2) R16.2 U8.8(~{RESET}) U10.1(A)
NetD4_2: D4.2(K) U6.5(2A) U6.7(1Y)
NetJ2_2: J2.2 R17.2 U8.5(SET1)
NetR15_1: R15.1 U8.2(CWD)
NetR19_1: R19.1 U8.7(~{WDO}) U10.3(B)
NetR21_2: R21.2 R22.1 U10.4(Y)
NetR26_1: R26.1 R27.1 U7.34(SPI3SOMI)
NetR27_2: R27.2 U13.11(IND)
NetTP7_1: TP7.1 U7.74(N2HET[8])
NetU7_35: U7.35(SPI3SIMO) U13.12(OUTC)
NetU7_36: U7.36(SPI3CLK) U13.13(OUTB)
NetU7_38: U7.38(SPI3~{CS}[0]) U13.14(OUTA)

Not connected (* = marked no-connect by the designer): J1 6*; U7 3(FLTP1)* 4(FLTP2)* 37(SPI3~{ENA})* 58(ADEVT)* 62(CAN1TX)* 63(CAN1RX)* 69(SPI2SOMI) 84(ECLK)* 91(CAN2TX)* 92(CAN2RX)* 94(LINRX)* 95(LINTX)*; U11 4(CT); U13 7(EN1)* 10(EN2)*

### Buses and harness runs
bus /DIAG_EN[1..8] = port /DIAG_EN[1..8]
bus DI_LOGIC[1..8] = port DI_LOGIC[1..8]
bus DIAG_CTRL[1..8] = port DIAG_CTRL[1..8]

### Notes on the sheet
- J2 jumper inserted: Watchdog enabled
  J2 jumper removed: Watchdog disabled
- WINDOWED WATCHDOG
- HERCULES POWER
- Window 2.2ms<t<9.3ms
- >40dB @ 600kHz
- (near U7) HERCULES
- ISOLATOR POWER DOWN
- ISOLATION
- During safe state, signal MASTER_SPI_MISO is low
- PIN 1, 2, 5, 9, 10: Internal PullDown-resistor enabled
  PIN 38: Internal PullUp-resistor enabled
  PIN 8: OpenDrain enabled

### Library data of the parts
C5 C10-C16 C21-C26 C28-C30 C33 = CMP-0007378-5: CAP, CERM, 0.1 uF, 16 V, +/- 10%, X7R, 0603; Manufacturer: MuRata; TaMin_C: -55°C; Polarized: N; SizeAreaWB_mm2: 4.68; Value1: Unknown; U/M: EA; Value: 0.1uF; TaMax_C: 125°C; SizeZ_mm: 1; SizeX_mm: 1.6; SizeY_mm: 0.8; SizeArea_mm2: 1.28; Cap_F: 100nF; AEC Category: Q200
C6-C9 C19 C20 = CMP-0064945-2: CAP, CERM, 10 uF, 6.3 V,+/- 10%, X7R, 0805; Manufacturer: Taiyo Yuden; TaMin_C: -55°C; Polarized: N; SizeAreaWB_mm2: 6.75; Value1: Unknown; U/M: EA; Value: 10uF; TaMax_C: 125°C; SizeZ_mm: 1.45; SizeX_mm: 2; SizeY_mm: 1.25; Cap_Case: 0805; SizeArea_mm2: 2.5; Cap_F: 10µF; AEC Category: Q200
C17 = CMP-0008377-2: CAP, CERM, 22 uF, 10 V, +/- 20%, X7R, 0805; Manufacturer: MuRata; SizeY_mm: 1.25; Cap_Case: 0805; SizeArea_mm2: 2.5; AEC Qualified: N; Cap_F: 22µF; AEC Category: Q200; TaMin_C: -55°C; SizeAreaWB_mm2: 6.75; Value1: Unknown; U/M: EA; Value: 22uF; TaMax_C: 125°C; SizeZ_mm: 1.45; SizeX_mm: 2
C18 C27 = CMP-0007365-4: CAP, CERM, 1 uF, 10 V, +/- 10%, X7R, 0603; Manufacturer: MuRata; TaMin_C: -55°C; ESR_ohm: 0.011; Polarized: N; SizeAreaWB_mm2: 4.68; Value1: 0.011 ohm; U/M: EA; Value: 1uF; TaMax_C: 125°C; SizeZ_mm: 1; SizeX_mm: 1.6; SizeY_mm: 0.8; SizeArea_mm2: 1.28; Cap_F: 1µF; AEC Category: Q200
C31 C32 = CMP-0007208-4: CAP, CERM, 33 pF, 50 V, +/- 5%, C0G/NP0, 0603; Manufacturer: MuRata; TaMin_C: -55°C; Polarized: N; SizeAreaWB_mm2: 4.68; Value1: Unknown; U/M: EA; Value: 33pF; TaMax_C: 125°C; SizeZ_mm: 1; SizeX_mm: 1.6; SizeY_mm: 0.8; Value2: 50V; SizeArea_mm2: 1.28; AEC Category: Q200
D2 = CMP-0086222-1: Diode, Switching, 30 V, 0.13 A, SOT23, 3-Leads, Body 2.98x1.6mm, Pitch 0.95mm; Manufacturer: Panasonic; AEC Qualified: N; Vr_V: 30V; Io_A: 130mA; Value1: 0.13A; SizeArea_mm2: 8.195; Value2: 0.55V; Vf_V: 550mV; AEC Category: Q101; SizeX_mm: 2.75; SizeY_mm: 2.98; TJmax_C: 125°C; Value: 30V; SizeZ_mm: 1.4; SizeAreaWB_mm2: 14.925
D3 = CMP-0028454-2: Diode, Schottky, 30 V, 0.2 A, SOT-523; Manufacturer: Diodes Inc.; AEC Category: Q101; Green_REACh: Incomplete; SizeAreaWB_mm2: 6.76; SizeY_mm: 1.6; SizeZ_mm: 0.8; Vr_V: 30V; Green_Lifecycle: Not Set; SizeArea_mm2: 2.56; TJmax_C: 125°C; Vf_V: 700mV; Value: 30V; Value2: 0.7V; Io_A: 200mA; Value1: 0.2A
D4 = CMP-0077018-2: Diode, Schottky, 30 V, 0.2 A, SOT-523; Manufacturer: Diodes Inc.; TJmax_C: 125°C; SizeX_mm: 1.6; SizeZ_mm: 0.8; Green_REACh: Incomplete; Value2: 1V; Io_A: 200mA; AEC Category: Q101; Green_Lifecycle: Not Set; Value: 30V; Value1: 0.2A; SizeAreaWB_mm2: 6.76; SizeArea_mm2: 2.56
J1 = CMP-0075640-2: Header, 1.27mm, 10x2, Tin, SMT; Manufacturer: Samtec; Pitch_mm: 1.27; Gender: Male; Cert_UL: Y; Green_REACh: Passed; Current_A: 3.1A; Shrouded: N; RowSpacing_mm: 2.54; Green_Lifecycle: Active; Row_Count: 2
J2 = CMP-0075483-1: Header, 100mil, 2x1, Gold, TH; Manufacturer: Samtec; Green_REACh: Passed; CT: False; Green_Lifecycle: Active; CNHeader: True
R8 R16 R22 R24 R27 = CMP-0025918-5: RES, 3.3 k, 5%, 0.1 W, 0603; Manufacturer: Yageo; Power_W: 100mW; TempCo: 100 ppm/C; Value_Code: 3k30; Value: 3.3k; EIA_Code: E24; SizeX_mm: 1.6; SizeY_mm: 0.8; SizeZ_mm: 1; Value2: 0.1W; SizeArea_mm2: 1.28; AEC Qualified: N; VDC_V: 75V; AEC Category: Q200; SizeAreaWB_mm2: 4.68
R9-R13 R15 R26 = CMP-0025886-5: RES, 10 k, 5%, 0.1 W, 0603; Manufacturer: Yageo; Power_W: 100mW; TempCo: 100 ppm/C; Value_Code: 10k0; Value: 10k; EIA_Code: E24; SizeX_mm: 1.6; SizeY_mm: 0.8; SizeZ_mm: 1; Value2: 0.1W; SizeArea_mm2: 1.28; AEC Qualified: N; VDC_V: 75V; AEC Category: Q200; SizeAreaWB_mm2: 4.68
R14 R17 R19 R21 R28 = CMP-0025925-5: RES, 47 k, 5%, 0.1 W, 0603; Manufacturer: Yageo; Power_W: 100mW; TempCo: 100 ppm/C; Value_Code: 47k0; Value: 47k; EIA_Code: E24; SizeX_mm: 1.6; SizeY_mm: 0.8; SizeZ_mm: 1; Value2: 0.1W; SizeArea_mm2: 1.28; AEC Qualified: N; VDC_V: 75V; AEC Category: Q200; SizeAreaWB_mm2: 4.68
R18 = CMP-0025821-4: RES, 4.7, 5%, 0.1 W, AEC-Q200 Grade 0, 0603; Manufacturer: Vishay-Dale; Power_W: 100mW; TempCo: 200 ppm/C; Value_Code: 4R70; Value: 4.7; EIA_Code: E24; SizeX_mm: 1.6; SizeY_mm: 0.8; SizeZ_mm: 1; Value2: 0.1W; SizeArea_mm2: 1.28; AEC Qualified: Y; VDC_V: 75V; AEC Category: Q200; AEC Grade: 0
R20 = CMP-0022984-5: RES, 2.21 k, 1%, 0.1 W, 0603; Manufacturer: Yageo; Power_W: 100mW; TempCo: 100 ppm/C; Value_Code: 2k21; Value: 2.21k; EIA_Code: E96; SizeX_mm: 1.6; SizeY_mm: 0.8; SizeZ_mm: 1; Value2: 0.1W; SizeArea_mm2: 1.28; AEC Qualified: N; VDC_V: 75V; AEC Category: Q200; SizeAreaWB_mm2: 4.68
R23 = CMP-0025752-3: RES, 200, 5%, 0.1 W, 0603; Manufacturer: Vishay-Dale; Power_W: 100mW; TempCo: 200 ppm/C; Value_Code: 200R; U/M: EA; Value: 200; EIA_Code: E24; SizeX_mm: 1.6; SizeY_mm: 0.8; SizeZ_mm: 1; Value2: 0.1W; SizeArea_mm2: 1.28; VDC_V: 75V; AEC Category: Q200
R25 = CMP-0025899-5: RES, 1.0 k, 5%, 0.1 W, 0603; Manufacturer: Yageo; Power_W: 100mW; TempCo: 100 ppm/C; Value_Code: 1k00; Value: 1.0k; EIA_Code: E24; Res_ohm: 1k; SizeX_mm: 1.6; SizeY_mm: 0.8; SizeZ_mm: 1; Value2: 0.1W; SizeArea_mm2: 1.28; AEC Qualified: N; VDC_V: 75V; AEC Category: Q200; SizeAreaWB_mm2: 4.68
S1 S2 = CMP-0002210-1: Switch, Tactile, SPST-NO, 0.05A, 12V, SMD; Manufacturer: C&K Components; CurrentRating_mA: 50A; PositionCount: 1; SwitchFunction: Off-Mom
TP6-TP9 = CMP-0003825-1: 1mm Test Point, SMT; Manufacturer: Any
TP11-TP14 = CMP-0055152-1: Test Point, Miniature, SMT; Manufacturer: Keystone; CNHeader: FALSE; Green_Lifecycle: Active; Green_REACh: Passed; CT: TRUE
U6 = CMP-0051919-2: Dual 2-Input NAND Gate with Schmitt-Trigger Inputs, DCU0008A (VSSOP-8); Manufacturer: Texas Instruments; Logic: True; Bits(#): 2; tpd @ Nom Voltage(Max)(ns): 16,7.5,6,5; VCC(Max)(V): 5.5; Technology Family: LVC; Rating: Catalog; Output Drive (IOL/IOH)(Max)(mA): 32/-32; Schmitt Trigger: Yes; Output Type: CMOS; VCC(Min)(V): 1.65; 3-State Output: No; ICC @ Nom Voltage(Max)(mA): 0.01; Input Type: CMOS/TTL; Voltage(Nom)(V): 1.8,2.5,3.3,5; F @ Nom Voltage(Max)(Mhz): 150; AEC Category: Q200; AEC Qualified: N; CompType: IC; SizeAreaWB_mm2: 12.6; SizeArea_mm2: 6.4; SizeX_mm: 3.2; SizeY_mm: 2.0; SizeZ_mm: 0.9
U7 = CMP-0076634-2: 16- and 32-Bit RISC Flash Microcontroller, PZ0100A (LQFP-100); Manufacturer: Texas Instruments; SizeZ_mm: 1.6; SizeX_mm: 16.0; SizeArea_mm2: 256.0; CompType: IC; U/M: EA; SizeAreaWB_mm2: 324.0
U8 = CMP-0013381-4: High-Accuracy Voltage Supervisor With Programmable Window Watchdog Timer, DRB0008A (VSON-8); Alternate PartNumber: TPS3852H33DRBT; Alternate Manufacturer: Texas Instruments; SizeX_mm: 3.0; AEC Qualified: N; CompType: IC; SizeArea_mm2: 9.0; SizeAreaWB_mm2: 16.0; SizeZ_mm: 1.0; Rating: Catalog; AEC Category: Q200
U9 = CMP-0032500-1: 3.0 V, 50 ppm / degC, 50 uA Series (Bandgap) Voltage Reference, -40 to 125 degC, 3-pin SOT-23 (DBZ), Green (RoHS & no Sb/Br); Manufacturer: Texas Instruments; SubFamily: Series Voltage Reference; Temp Coeff(Typ)(ppm/ degree C): 20; Rating: Catalog; Temp Coeff(Max)(ppm/ degree C): 50
U10 = CMP-0051216-3: Single 3-Input Positive-AND Gate, DCK0006A (SOT-SC70-6); Manufacturer: Texas Instruments; Output Type: CMOS; Bits(#): 1; Input Type: CMOS/TTL; Technology Family: LVC; Schmitt Trigger: No; VCC(Max)(V): 5.5; Gate Type: AND; Rating: Catalog; Output Drive (IOL/IOH)(Max)(mA): 32/-32; ICC @ Nom Voltage(Max)(mA): 0.01; VCC(Min)(V): 1.65; F @ Nom Voltage(Max)(Mhz): 150; Logic: True; Voltage(Nom)(V): 1.8,2.5,3.3,5; tpd @ Nom Voltage(Max)(ns): 20,7.8,6.2,4.6; AEC Category: Q200; AEC Qualified: N; CompType: IC; SizeAreaWB_mm2: 9.3; SizeArea_mm2: 4.2; SizeX_mm: 2.1; SizeY_mm: 2.0; SizeZ_mm: 1.1
U11 = CMP-0077265-1: 5.5-V, 2-A, 80 mohm Low Leakage Load Switch with RCB and Programmable Rise Time, DBV0006A (SOT-23-6); Alternate PartNumber: TPS22917DBVT; Alternate Manufacturer: Texas Instruments; SizeAreaWB_mm2: 14.82; SizeZ_mm: 1.45; SizeX_mm: 2.8; SizeY_mm: 2.9; SizeArea_mm2: 8.12; CompType: IC; AEC Qualified: N; AEC Category: Q200
U12 = CMP-0084725-1: Programmable Shunt Regulator with Optimized Reference Current, DBZ0003A (SOT-23-3); Manufacturer: Texas Instruments; SizeZ_mm: 1.12; CompType: IC; SizeX_mm: 2.5; SizeY_mm: 3; SizeAreaWB_mm2: 14; AEC Category: Q200; SizeArea_mm2: 7.5; AEC Qualified: N
U13 = CMP-0076065-3: Automotive, High Speed, Robust EMC Quad-Channel Digital Isolators, DW0016B (SOIC-16); Manufacturer: Texas Instruments; Alternate PartNumber: ISO7741FQDWQ1; CompType: IC; SizeAreaWB_mm2: 152.52; SizeY_mm: 10.3; SizeArea_mm2: 107.12; SizeZ_mm: 2.65; AEC Category: Q200; AEC Qualified: Y; SizeX_mm: 10.4
Y1 = CMP-0004648-3: Crystal, 16 MHz, 18 pF, SMD; Manufacturer: Abracon Corporation; TaMin_C: -40°C; Frequency Stability: +/-30ppm; Frequency_Fixed: 16MHz; TaMax_C: 85°C

## Sheet TIDA-010049_Power.SchDoc
size 431 x 279 mm; Date: Not shown in title block; ApprovedBy: Not shown in title block; CheckedBy: Not shown in title block; Author: Not shown in title block; CompanyName: Not shown in title block; Engineer: Not shown in title block; Organization: Not shown in title block; Address1: Not shown in title block; Address2: Not shown in title block; Address3: Not shown in title block; Address4: Not shown in title block; DocumentNumber: 2; Revision: Use project parameter SCH_Rev; SheetNumber: 2; SheetTotal: 3; PageSetup: Record=PageOptions¦CenterHorizontal=True¦CenterVertical=True¦PrintScale=1.00¦XCorrection=1.00¦YCorrection=1.00¦PrintKind=0¦BorderSize=5000000¦LeftOffset=0¦BottomOffset=0¦Orientation=2¦PaperLength=1000¦PaperWidth=1000¦Scale=100¦PaperSource=15¦PrintQuality=600¦MediaType=1¦DitherType=10¦PaperKind=Letter¦PrintScaleMode=1
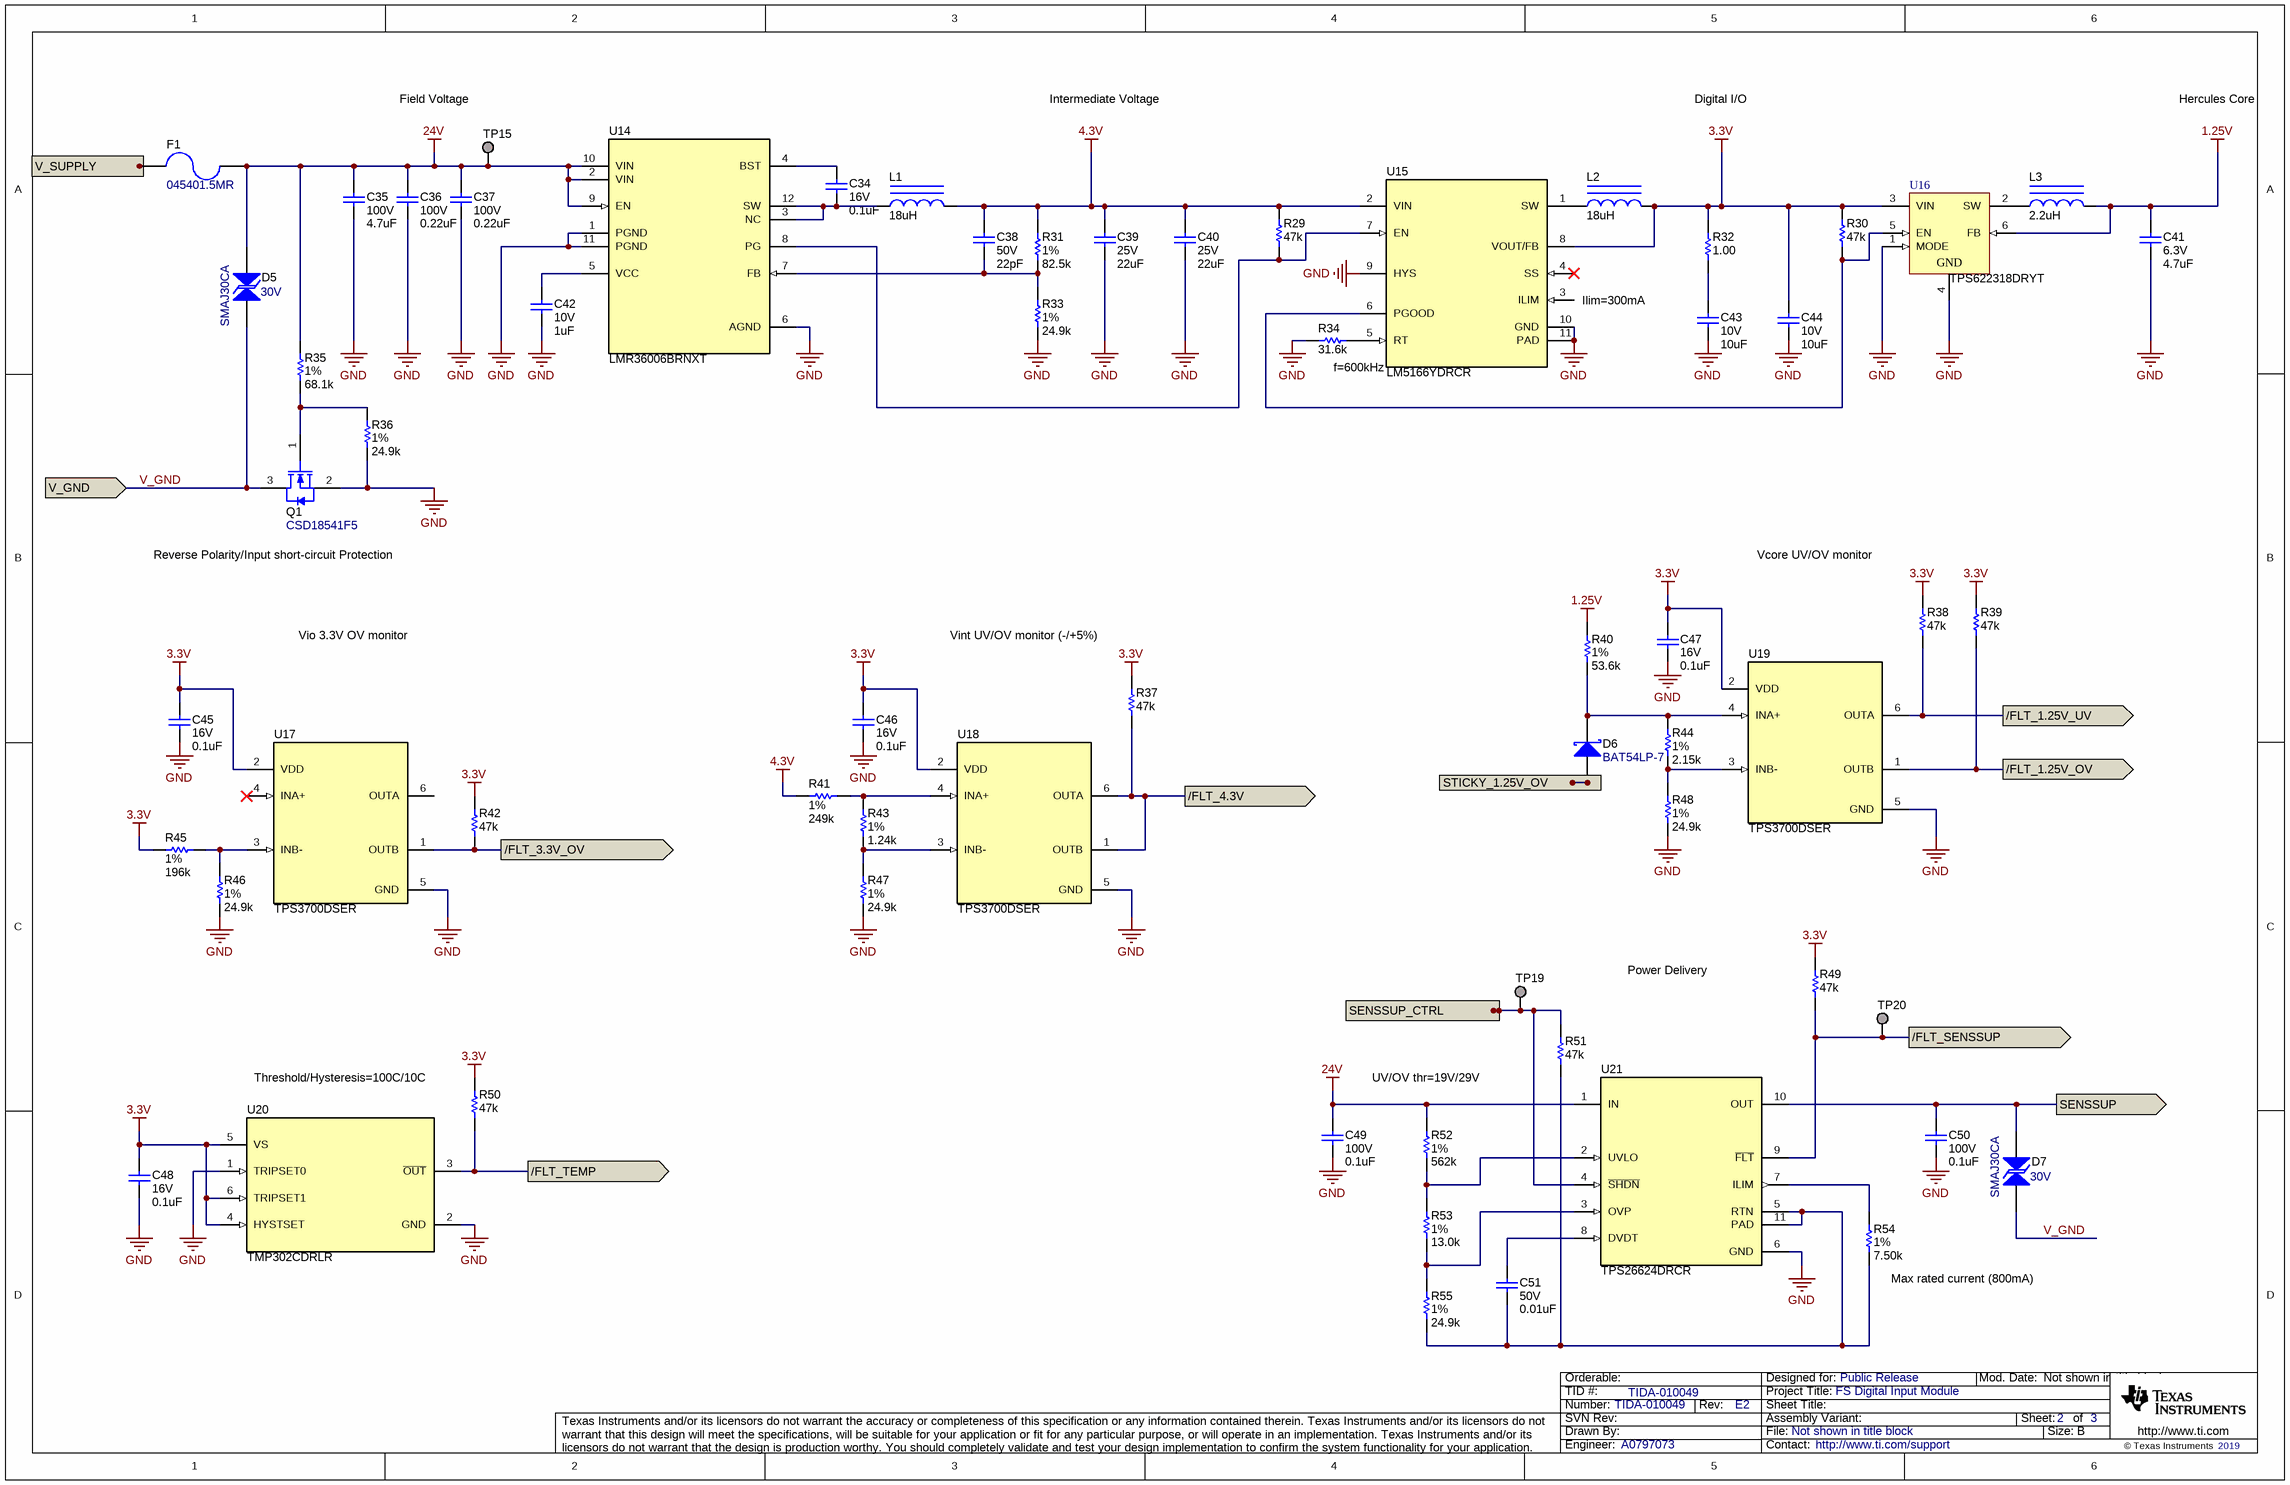
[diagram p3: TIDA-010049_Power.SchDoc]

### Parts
C34  VDC_V: 16V  ValueDisplayed: 0.1uF  [0603]  (hidden comment: GRM188R71C104KA01D)
C35  VDC_V: 100V  ValueDisplayed: 4.7uF  [2220_250]  (hidden comment: C5750X7R2A475K230KA)
C36  VDC_V: 100V  ValueDisplayed: 0.22uF  [0805_HV]  (hidden comment: GRM21AR72A224KAC5L)
C37  VDC_V: 100V  ValueDisplayed: 0.22uF  [0805_HV]  (hidden comment: GRM21AR72A224KAC5L)
C38  VDC_V: 50V  ValueDisplayed: 22pF  [0603]  (hidden comment: GRM1885C1H220JA01D)
C39  VDC_V: 25V  ValueDisplayed: 22uF  [1812_280]  (hidden comment: C4532X7R1E226M250KC)
C40  VDC_V: 25V  ValueDisplayed: 22uF  [1812_280]  (hidden comment: C4532X7R1E226M250KC)
C41  VDC_V: 6.3V  ValueDisplayed: 4.7uF  [0603]  (hidden comment: CL10B475KQ8NQND)
C42  VDC_V: 10V  ValueDisplayed: 1uF  [0603]  (hidden comment: GRM188R71A105KA61D)
C43  VDC_V: 10V  ValueDisplayed: 10uF  [0805_HV]  (hidden comment: GRM21BR71A106KE51L)
C44  VDC_V: 10V  ValueDisplayed: 10uF  [0805_HV]  (hidden comment: GRM21BR71A106KE51L)
C45  VDC_V: 16V  ValueDisplayed: 0.1uF  [0603]  (hidden comment: GRM188R71C104KA01D)
C46  VDC_V: 16V  ValueDisplayed: 0.1uF  [0603]  (hidden comment: GRM188R71C104KA01D)
C47  VDC_V: 16V  ValueDisplayed: 0.1uF  [0603]  (hidden comment: GRM188R71C104KA01D)
C48  VDC_V: 16V  ValueDisplayed: 0.1uF  [0603]  (hidden comment: GRM188R71C104KA01D)
C49  VDC_V: 100V  ValueDisplayed: 0.1uF  [0603]
C50  VDC_V: 100V  ValueDisplayed: 0.1uF  [0603]
C51  VDC_V: 50V  ValueDisplayed: 0.01uF  [0603]
D5  SMAJ30CA  value 30V  [SMA_Bi]
D6  BAT54LP-7  [X1-DFN1006-2]
D7  SMAJ30CA  value 30V  [SMA_Bi]
F1  045401.5MR  [SloBlo452]
L1  ValueDisplayed: 18uH  [WE-TPC_4828]  (hidden comment: 744043180)
L2  ValueDisplayed: 18uH  [WE-TPC_4828]  (hidden comment: 744043180)
L3  ValueDisplayed: 2.2uH  [0805_HV]  (hidden comment: LQM21PN2R2MC0D)
Q1  CSD18541F5  [YJK0003A]
R29  ValueDisplayed: 47k  [0603]  (hidden comment: RC0603JR-0747KL)
R30  ValueDisplayed: 47k  [0603]  (hidden comment: RC0603JR-0747KL)
R31  Tolerance_%: 1%  ValueDisplayed: 82.5k  [0603]  (hidden comment: RC0603FR-0782K5L)
R32  ValueDisplayed: 1.00  [0603]  (hidden comment: RC0603FR-071RL)
R33  Tolerance_%: 1%  ValueDisplayed: 24.9k  [0603]  (hidden comment: RC0603FR-0724K9L)
R34  ValueDisplayed: 31.6k  [0603]  (hidden comment: RC0603FR-0731K6L)
R35  Tolerance_%: 1%  ValueDisplayed: 68.1k  [0603]  (hidden comment: RC0603FR-0768K1L)
R36  Tolerance_%: 1%  ValueDisplayed: 24.9k  [0603]  (hidden comment: RC0603FR-0724K9L)
R37  ValueDisplayed: 47k  [0603]  (hidden comment: RC0603JR-0747KL)
R38  ValueDisplayed: 47k  [0603]  (hidden comment: RC0603JR-0747KL)
R39  ValueDisplayed: 47k  [0603]  (hidden comment: RC0603JR-0747KL)
R40  Tolerance_%: 1%  ValueDisplayed: 53.6k  [0603]  (hidden comment: RC0603FR-0753K6L)
R41  Tolerance_%: 1%  ValueDisplayed: 249k  [0603]  (hidden comment: RC0603FR-07249KL)
R42  ValueDisplayed: 47k  [0603]  (hidden comment: RC0603JR-0747KL)
R43  Tolerance_%: 1%  ValueDisplayed: 1.24k  [0603]  (hidden comment: RC0603FR-071K24L)
R44  Tolerance_%: 1%  ValueDisplayed: 2.15k  [0603]  (hidden comment: RC0603FR-072K15L)
R45  Tolerance_%: 1%  ValueDisplayed: 196k  [0603]  (hidden comment: RC0603FR-07196KL)
R46  Tolerance_%: 1%  ValueDisplayed: 24.9k  [0603]  (hidden comment: RC0603FR-0724K9L)
R47  Tolerance_%: 1%  ValueDisplayed: 24.9k  [0603]  (hidden comment: RC0603FR-0724K9L)
R48  Tolerance_%: 1%  ValueDisplayed: 24.9k  [0603]  (hidden comment: RC0603FR-0724K9L)
R49  ValueDisplayed: 47k  [0603]  (hidden comment: RC0603JR-0747KL)
R50  ValueDisplayed: 47k  [0603]  (hidden comment: RC0603JR-0747KL)
R51  ValueDisplayed: 47k  [0603]  (hidden comment: RC0603JR-0747KL)
R52  Tolerance_%: 1%  ValueDisplayed: 562k  [0603]  (hidden comment: RC0603FR-07562KL)
R53  Tolerance_%: 1%  ValueDisplayed: 13.0k  [0603]  (hidden comment: RC0603FR-0713KL)
R54  Tolerance_%: 1%  ValueDisplayed: 7.50k  [0603]  (hidden comment: RC0603FR-077K5L)
R55  Tolerance_%: 1%  ValueDisplayed: 24.9k  [0603]  (hidden comment: RC0603FR-0724K9L)
TP15  TP_SM_1MM  [TP_SM_1MM]  (value not drawn)  (no BOM)
TP19  TP_SM_1MM  [TP_SM_1MM]  (value not drawn)  (no BOM)
TP20  TP_SM_1MM  [TP_SM_1MM]  (value not drawn)  (no BOM)
U14  LMR36006BRNXT  [RNX0012B]
U15  LM5166YDRCR  [DRC0010J]
U16  TPS622318DRYT  [DRY0006A]
U17  TPS3700DSER  [DSE0006A]
U18  TPS3700DSER  [DSE0006A]
U19  TPS3700DSER  [DSE0006A]
U20  TMP302CDRLR  [DRL0006A]
U21  TPS26624DRCR  [DRC0010J]

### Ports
/FLT_1.25V_OV (out), /FLT_1.25V_UV (out), /FLT_3.3V_OV (out), /FLT_4.3V (out), /FLT_SENSSUP (out), /FLT_TEMP (out), SENSSUP (out), SENSSUP_CTRL (in), STICKY_1.25V_OV (in), V_GND (in), V_SUPPLY (in)

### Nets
1.25V: C41.1 L3.2 R40.1 U16.6(FB)
3.3V: C44.1 C45.1 C46.1 C47.1 C48.1 L2.2 R30.1 R32.2 R37.1 R38.2 R39.2 R42.1 R45.2 R49.2 R50.1 U15.8(VOUT/FB) U16.3(VIN) U17.2(VDD) U18.2(VDD) U19.2(VDD) U20.4(HYSTSET) U20.5(VS) U20.6(TRIPSET1)
4.3V: C38.1 C39.1 C40.1 L1.2 R29.1 R31.1 R41.1 U15.2(VIN)
24V: C35.1 C36.1 C37.1 C49.1 D5.2 F1.1 R35.2 R52.1 TP15.1 U14.2(VIN) U14.9(EN) U14.10(VIN) U21.1(IN)
GND: C35.2 C36.2 C37.2 C39.2 C40.2 C41.2 C42.2 C43.2 C44.2 C45.2 C46.2 C47.2 C48.2 C49.2 C50.2 Q1.2(S) R33.2 R34.2 R36.2 R46.2 R47.2 R48.2 U14.1(PGND) U14.6(AGND) U14.11(PGND) U15.9(HYS) U15.10(GND) U15.11(PAD) U16.1(MODE) U16.4(GND) U17.5(GND) U18.5(GND) U19.5(GND) U20.1(TRIPSET0) U20.2(GND) U21.6(GND)
/FLT_1.25V_OV: R39.1 U19.1(OUTB) ; port /FLT_1.25V_OV
/FLT_1.25V_UV: R38.1 U19.6(OUTA) ; port /FLT_1.25V_UV
/FLT_3.3V_OV: R42.2 U17.1(OUTB) ; port /FLT_3.3V_OV
/FLT_4.3V: R37.2 U18.1(OUTB) U18.6(OUTA) ; port /FLT_4.3V
/FLT_SENSSUP: R49.1 TP20.1 U21.9(~{FLT}) ; port /FLT_SENSSUP
/FLT_TEMP: R50.2 U20.3(~{OUT}) ; port /FLT_TEMP
SENSSUP: C50.1 D7.2 U21.10(OUT) ; port SENSSUP
SENSSUP_CTRL: R51.2 TP19.1 U21.4(~{SHDN}) ; port SENSSUP_CTRL
V_GND: D5.1 D7.1 Q1.3(D) ; port V_GND
NetC34_1: C34.1 U14.4(BST)
NetC34_2: C34.2 L1.1 U14.3(NC) U14.12(SW)
NetC38_2: C38.2 R31.2 R33.1 U14.7(FB)
NetC42_1: C42.1 U14.5(VCC)
NetC43_1: C43.1 R32.1
NetC51_1: C51.1 U21.8(DVDT)
NetC51_2: C51.2 R51.1 R54.2 R55.2 U21.5(RTN) U21.11(PAD)
NetD6_1: D6.1(K) R40.2 R44.1 U19.4(INA+)
NetL2_1: L2.1 U15.1(SW)
NetL3_1: L3.1 U16.2(SW)
NetQ1_1: Q1.1(G) R35.1 R36.1
NetR29_2: R29.2 U14.8(PG) U15.7(EN)
NetR30_2: R30.2 U15.6(PGOOD) U16.5(EN)
NetR34_1: R34.1 U15.5(RT)
NetR41_2: R41.2 R43.1 U18.4(INA+)
NetR43_2: R43.2 R47.1 U18.3(INB-)
NetR44_2: R44.2 R48.1 U19.3(INB-)
NetR45_1: R45.1 R46.1 U17.3(INB-)
NetR52_2: R52.2 R53.1 U21.2(UVLO)
NetR53_2: R53.2 R55.1 U21.3(OVP)
NetR54_1: R54.1 U21.7(ILIM)

Not connected (* = marked no-connect by the designer): D6 2(A); F1 2; U15 3(ILIM) 4(SS)*; U17 4(INA+)* 6(OUTA)

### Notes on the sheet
- (near TP15) Field Voltage
- Intermediate Voltage
- Digital I/O
- Hercules Core
- (near U15) Ilim=300mA
- f=600kHz
- Reverse Polarity/Input short-circuit Protection
- Vcore UV/OV monitor
- Vio 3.3V OV monitor
- Vint UV/OV monitor (-/+5%)
- Power Delivery
- Threshold/Hysteresis=100C/10C
- UV/OV thr=19V/29V
- (near R54) Max rated current (800mA)

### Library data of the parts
C34 C45-C48 = CMP-0007378-5: as C5 on sheet TIDA-010049_Hercules
C35 = CMP-0009384-2: CAP, CERM, 4.7 uF, 100 V, +/- 10%, X7R,; Manufacturer: TDK; TaMin_C: -55°C; ESR_ohm: 2.349m; Polarized: N; SizeAreaWB_mm2: 53.9; Value1: 0.002349 ohm; U/M: EA; Value: 4.7uF; TaMax_C: 125°C; SizeZ_mm: 2.5; SizeX_mm: 5.7; SizeY_mm: 5; SizeArea_mm2: 28.5; Cap_F: 4.7µF; IRMS_A: 5.95718A; AEC Category: Q200
C36 C37 = CMP-0008249-2: CAP, CERM, 0.22 uF, 100 V, +/- 10%, X7R, 0805; Manufacturer: MuRata; TaMin_C: -55°C; Polarized: N; SizeAreaWB_mm2: 6.75; Value1: Unknown; U/M: EA; Value: 0.22uF; TaMax_C: 125°C; SizeZ_mm: 1.45; SizeX_mm: 2; SizeY_mm: 1.25; Cap_Case: 0805; SizeArea_mm2: 2.5; Cap_F: 220nF; AEC Category: Q200
C38 = CMP-0007196-4: CAP, CERM, 22 pF, 50 V, +/- 5%, C0G/NP0, 0603; Manufacturer: MuRata; TaMin_C: -55°C; Polarized: N; SizeAreaWB_mm2: 4.68; Value1: Unknown; U/M: EA; Value: 22pF; TaMax_C: 125°C; SizeZ_mm: 1; SizeX_mm: 1.6; SizeY_mm: 0.8; SizeArea_mm2: 1.28; AEC Category: Q200
C39 C40 = CMP-0009348-2: CAP, CERM, 22 uF, 25 V, +/- 20%, X7R,; Manufacturer: TDK; TaMin_C: -55°C; ESR_ohm: 2.434m; Polarized: N; SizeAreaWB_mm2: 23.1; Value1: 0.002434 ohm; U/M: EA; Value: 22uF; TaMax_C: 125°C; SizeZ_mm: 2.8; SizeX_mm: 4.5; SizeY_mm: 3.2; SizeArea_mm2: 14.4; Cap_F: 22µF; IRMS_A: 4.91649A; AEC Category: Q200
C41 = CMP-0007112-4: CAP, CERM, 4.7 uF, 6.3 V, +/- 10%, X7R, 0603; Manufacturer: Samsung; TaMin_C: -55°C; Polarized: N; SizeAreaWB_mm2: 4.68; Value1: Unknown; U/M: EA; Value: 4.7uF; TaMax_C: 125°C; SizeZ_mm: 1; SizeX_mm: 1.6; SizeY_mm: 0.8; SizeArea_mm2: 1.28; Cap_F: 4.7µF; AEC Category: Q200
C42 = CMP-0007365-4: as C18 on sheet TIDA-010049_Hercules
C43 C44 = CMP-0008315-2: CAP, CERM, 10 uF, 10 V, +/- 10%, X7R, 0805; Manufacturer: MuRata; TaMin_C: -55°C; ESR_ohm: 3m; Polarized: N; SizeAreaWB_mm2: 6.75; Value1: 0.003 ohm; U/M: EA; Value: 10uF; TaMax_C: 125°C; SizeZ_mm: 1.45; SizeX_mm: 2; SizeY_mm: 1.25; Cap_Case: 0805; SizeArea_mm2: 2.5; Cap_F: 10µF; AEC Category: Q200
C49 C50 = CMP-0007469-4: CAP, CERM, 0.1 uF, 100 V, +/- 10%, X7R, 0603; Manufacturer: MuRata; PartNumber: GRM188R72A104KA35D; TaMin_C: -55°C; Polarized: N; SizeAreaWB_mm2: 4.68; Value1: Unknown; U/M: EA; Value: 0.1uF; TaMax_C: 125°C; SizeZ_mm: 1; SizeX_mm: 1.6; SizeY_mm: 0.8; SizeArea_mm2: 1.28; Cap_F: 100nF; AEC Category: Q200
C51 = CMP-0007109-4: CAP, CERM, 0.01 uF, 50 V, +/- 10%, X7R, 0603; Manufacturer: Samsung Electro-Mechanics; PartNumber: CL10B103KB8NCNC; TaMin_C: -55°C; Polarized: N; SizeAreaWB_mm2: 4.68; Value1: Unknown; U/M: EA; Value: 0.01uF; TaMax_C: 125°C; SizeZ_mm: 1; SizeX_mm: 1.6; SizeY_mm: 0.8; SizeArea_mm2: 1.28; Cap_F: 10nF; AEC Category: Q200
D5 D7 = CMP-0085015-1: Diode, TVS, Bi, 30 V, 48.4 Vc, 400 W, 8.3 A, SMA (non-polarized); Manufacturer: Littelfuse; SizeX_mm: 5.075; Value1: 48.4V; Ipp: 8.3A; AEC Category: Q101; SizeArea_mm2: 13.068125; Vbr_Min: 33.3V; AEC Qualified: N; SizeZ_mm: 2.65; Vbr_Max: 36.8V; SizeAreaWB_mm2: 32.368125; RJA_CperW: 120; SizeY_mm: 2.575; Ppk: 400W
D6 = CMP-0076931-2: Diode, Schottky, 30 V, 0.2 A, 1.00x0.50x0.60mm; Manufacturer: Diodes Inc.; Vr_V: 30V; SizeX_mm: 1.0; SizeZ_mm: 0.53; Io_A: 200mA; Value: 30V; Vf_V: 1V; AEC Category: Q101; Green_Lifecycle: Not Set; SizeAreaWB_mm2: 3.2; Value1: 0.2A; Green_REACh: Incomplete; SizeY_mm: 0.6
F1 = CMP-0003488-1: Fuse, 1.5 A, 125VAC/VDC, SMD; Manufacturer: Littelfuse; MeltingTyp: 3.65; Irating_A: 1.5A; Rtyp_Ohm: 0.093; VAC_V: 125V; Interrupt_AC: 50A
L1 L2 = CMP-0064407-2: Inductor, Shielded Drum Core, Ferrite, 18 uH, 0.7 A, 0.138 ohm, SMD; Manufacturer: Wurth Elektronik; Isat: 0.7A @ 35% inductance drop; Irms: 0.98A @ 30C rise; Green_Lifecycle: Active; SizeAreaWB_mm2: 33.64; DCR_ohm: 0.138; Green_REACh: Passed; Value: 18uH; Imax_A: 700mA; SizeZ_mm: 3; SizeX_mm: 4.8; Value2: 0.7A; SizeArea_mm2: 23.04; Ind_H: 18µH; AEC Category: Q200
L3 = CMP-0058743-1: Inductor, Multilayer, Ferrite, 2.2 uH, 0.6 A, 0.34 ohm, SMD; Manufacturer: MuRata; Irms: 0.6A @ 40C rise; Green_Lifecycle: Active; SizeAreaWB_mm2: 6.75; DCR_ohm: 0.34; Green_REACh: Passed; Value: 2.2uH; Imax_A: 600mA; SizeZ_mm: 1.45; SizeX_mm: 2; SizeY_mm: 1.25; Value2: 0.6A; SizeArea_mm2: 2.5; Ind_H: 2.2µH; AEC Category: Q200
Q1 = CMP-0000824-1: MOSFET, N-CH, 60 V, 2.2 A, YJK0003A (PICOSTAR-3); Alternate Manufacturer: None; Manufacturer: Texas Instruments; SizeZ_mm: 0.35; ChType: N; Value2: 11 nC; Value1: 0.07; VdsMax_V: 60V; SizeX_mm: 1.49; SizeY_mm: 0.73; Vgs_V: 20V; Value: 60V; Rdson45_ohm: 0.075; SizeArea_mm2: 1.0877; AEC Category: Q101; IdsMax_A: 2.2A; SizeAreaWB_mm2: 4.3077; U/M: EA; QgTyp_nC: 11
R29 R30 R37-R39 R42 R49-R51 = CMP-0025925-5: as R14 on sheet TIDA-010049_Hercules
R31 = CMP-0023291-5: RES, 82.5 k, 1%, 0.1 W, 0603; Manufacturer: Yageo; Power_W: 100mW; TempCo: 100 ppm/C; Value_Code: 82k5; Value: 82.5k; EIA_Code: E96; SizeX_mm: 1.6; SizeY_mm: 0.8; SizeZ_mm: 1; Value2: 0.1W; SizeArea_mm2: 1.28; AEC Qualified: N; VDC_V: 75V; AEC Category: Q200; SizeAreaWB_mm2: 4.68
R32 = CMP-0022900-4: RES, 1.00, 1%, 0.1 W, 0603; Manufacturer: Yageo; Power_W: 100mW; TempCo: 200 ppm/C; Value_Code: 1R00; Value: 1.00; EIA_Code: E96; Res_ohm: 1; SizeX_mm: 1.6; SizeY_mm: 0.8; Value2: 0.1W; SizeArea_mm2: 1.28; AEC Qualified: N; VDC_V: 75V; AEC Category: Q200; SizeAreaWB_mm2: 4.68
R33 R36 R46-R48 R55 = CMP-0022944-5: RES, 24.9 k, 1%, 0.1 W, 0603; Manufacturer: Yageo; Power_W: 100mW; TempCo: 100 ppm/C; Value_Code: 24k9; Value: 24.9k; EIA_Code: E96; SizeX_mm: 1.6; SizeY_mm: 0.8; SizeZ_mm: 1; Value2: 0.1W; SizeArea_mm2: 1.28; AEC Qualified: N; VDC_V: 75V; AEC Category: Q200; SizeAreaWB_mm2: 4.68
R34 = CMP-0023026-5: RES, 31.6 k, 1%, 0.1 W, 0603; Manufacturer: Yageo; Power_W: 100mW; TempCo: 100 ppm/C; Value_Code: 31k6; Value: 31.6k; EIA_Code: E96; SizeX_mm: 1.6; SizeY_mm: 0.8; SizeZ_mm: 1; Value2: 0.1W; SizeArea_mm2: 1.28; AEC Qualified: N; VDC_V: 75V; AEC Category: Q200; SizeAreaWB_mm2: 4.68
R35 = CMP-0023238-5: RES, 68.1 k, 1%, 0.1 W, 0603; Manufacturer: Yageo; Power_W: 100mW; TempCo: 100 ppm/C; Value_Code: 68k1; Value: 68.1k; EIA_Code: E96; SizeX_mm: 1.6; SizeY_mm: 0.8; SizeZ_mm: 1; Value2: 0.1W; SizeArea_mm2: 1.28; AEC Qualified: N; VDC_V: 75V; AEC Category: Q200; SizeAreaWB_mm2: 4.68
R40 = CMP-0023176-5: RES, 53.6 k, 1%, 0.1 W, 0603; Manufacturer: Yageo; Power_W: 100mW; TempCo: 100 ppm/C; Value_Code: 53k6; Value: 53.6k; EIA_Code: E96; SizeX_mm: 1.6; SizeY_mm: 0.8; SizeZ_mm: 1; Value2: 0.1W; SizeArea_mm2: 1.28; AEC Qualified: N; VDC_V: 75V; AEC Category: Q200; SizeAreaWB_mm2: 4.68
R41 = CMP-0022941-4: RES, 249 k, 1%, 0.1 W, 0603; Manufacturer: Yageo; Power_W: 100mW; TempCo: 100 ppm/C; Value: 249k; EIA_Code: E96; SizeX_mm: 1.6; SizeY_mm: 0.8; SizeZ_mm: 1; Value2: 0.1W; SizeArea_mm2: 1.28; AEC Qualified: N; VDC_V: 75V; AEC Category: Q200; SizeAreaWB_mm2: 4.68
R43 = CMP-0022872-5: RES, 1.24 k, 1%, 0.1 W, 0603; Manufacturer: Yageo; Power_W: 100mW; TempCo: 100 ppm/C; Value_Code: 1k24; Value: 1.24k; EIA_Code: E96; SizeX_mm: 1.6; SizeY_mm: 0.8; SizeZ_mm: 1; Value2: 0.1W; SizeArea_mm2: 1.28; AEC Qualified: N; VDC_V: 75V; AEC Category: Q200; SizeAreaWB_mm2: 4.68
R44 = CMP-0022982-5: RES, 2.15 k, 1%, 0.1 W, 0603; Manufacturer: Yageo; Power_W: 100mW; TempCo: 100 ppm/C; Value_Code: 2k15; Value: 2.15k; EIA_Code: E96; SizeX_mm: 1.6; SizeY_mm: 0.8; SizeZ_mm: 1; Value2: 0.1W; SizeArea_mm2: 1.28; AEC Qualified: N; VDC_V: 75V; AEC Category: Q200; SizeAreaWB_mm2: 4.68
R45 = CMP-0022858-4: RES, 196 k, 1%, 0.1 W, 0603; Manufacturer: Yageo; Power_W: 100mW; TempCo: 100 ppm/C; Value: 196k; EIA_Code: E96; SizeX_mm: 1.6; SizeY_mm: 0.8; SizeZ_mm: 1; Value2: 0.1W; SizeArea_mm2: 1.28; AEC Qualified: N; VDC_V: 75V; AEC Category: Q200; SizeAreaWB_mm2: 4.68
R52 = CMP-0023184-4: RES, 562 k, 1%, 0.1 W, 0603; Manufacturer: Yageo; Power_W: 100mW; TempCo: 100 ppm/C; Value: 562k; EIA_Code: E96; SizeX_mm: 1.6; SizeY_mm: 0.8; SizeZ_mm: 1; Value2: 0.1W; SizeArea_mm2: 1.28; AEC Qualified: N; VDC_V: 75V; AEC Category: Q200; SizeAreaWB_mm2: 4.68
R53 = CMP-0022792-5: RES, 13.0 k, 1%, 0.1 W, 0603; Manufacturer: Yageo; Power_W: 100mW; TempCo: 100 ppm/C; Value_Code: 13k0; Value: 13.0k; EIA_Code: E96; Res_ohm: 13k; SizeX_mm: 1.6; SizeY_mm: 0.8; SizeZ_mm: 1; Value2: 0.1W; SizeArea_mm2: 1.28; AEC Qualified: N; VDC_V: 75V; AEC Category: Q200; SizeAreaWB_mm2: 4.68
R54 = CMP-0023279-5: RES, 7.50 k, 1%, 0.1 W, 0603; Manufacturer: Yageo; Power_W: 100mW; TempCo: 100 ppm/C; Value_Code: 7k50; Value: 7.50k; EIA_Code: E96; Res_ohm: 7.5k; SizeX_mm: 1.6; SizeY_mm: 0.8; SizeZ_mm: 1; Value2: 0.1W; SizeArea_mm2: 1.28; AEC Qualified: N; VDC_V: 75V; AEC Category: Q200; SizeAreaWB_mm2: 4.68
TP15 TP19 TP20 = CMP-0003825-1: 1mm Test Point, SMT; Manufacturer: Any
U14 = CMP-0080116-3: 65-V 0.6-A Synchronous Step-Down Converter, RNX0012B (VQFN-HR-12); Alternate Manufacturer: Texas Instruments; Alternate PartNumber: LMR36006BRNXR; AEC Category: Q200; SizeAreaWB_mm2: 12.0; SizeX_mm: 2.0; CompType: IC; SizeArea_mm2: 6.0; SizeZ_mm: 0.9; SizeY_mm: 3.0; AEC Qualified: N
U15 = CMP-0013400-5: 3V-65V Input, 500mA Synchronous Buck Converter With Ultra-Low Iq, DRC0010J (VSON-10); Alternate PartNumber: LM5166YDRCT; Manufacturer: Texas Instruments; SizeZ_mm: 1; SizeX_mm: 3; SizeArea_mm2: 9; CompType: IC; SizeAreaWB_mm2: 16; AEC Category: Q200; AEC Qualified: N; Rating: Catalog
U16 = CMP-0037816-3: 2 MHz Ultra Small Step Down Converter with DCS-Control in 1x1.5 SON Package, DRY0006A (USON-6); Manufacturer: Texas Instruments; Eco-Plan: Green (RoHS & no Sb/Br); Rating: Catalog; Topology: Buck; Vout(Min)(V): 1.25; Duty Cycle(Max)(%): 100; Vin(Min)(V): 2.05; Switch Current Limit(Typ)(A): 0.84; Regulated Outputs(#): 1; Synchronous Rectification: TRUE; Iq(Typ)(mA): 0.022; Iout(Max)(A): 0.5; Vin(Max)(V): 6; AEC Category: Q200; AEC Qualified: N; CompType: IC; SizeAreaWB_mm2: 4.9; SizeArea_mm2: 1.45; SizeX_mm: 1.0; SizeZ_mm: 0.6
U17-U19 = CMP-0074243-1: High-Voltage (18V) Window Comparator with Over- and Undervoltage Detection, DSE0006A (WSON-6); Alternate PartNumber: TPS3700DSET; Alternate Manufacturer: Texas Instruments; Green_Lifecycle: Active; SizeAreaWB_mm2: 6.25; Green_REACh: Passed; U/M: EA; SizeZ_mm: 0.8; SizeX_mm: 1.5; SizeArea_mm2: 2.25; CompType: IC
U20 = CMP-0074324-2: Pin-Selectable Trip Point 1.4V-Capable Family of Temperature Switches, DRL0006A (SOT-OTHER-6); Alternate PartNumber: TMP302CDRLT; Manufacturer: Texas Instruments; SizeZ_mm: 0.6; SizeX_mm: 1.6; SizeArea_mm2: 2.56; CompType: IC; U/M: EA; SizeAreaWB_mm2: 6.76
U21 = CMP-0013390-6: 60-V, 800-mA Industrial eFuse with Integrated Reverse Polarity Protection, DRC0010J (VSON-10); Alternate PartNumber: TPS26624DRCT; Manufacturer: Texas Instruments; SizeZ_mm: 1; SizeX_mm: 3; SizeArea_mm2: 9; CompType: IC; SizeAreaWB_mm2: 16; AEC Category: Q200; AEC Qualified: N; Rating: Catalog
